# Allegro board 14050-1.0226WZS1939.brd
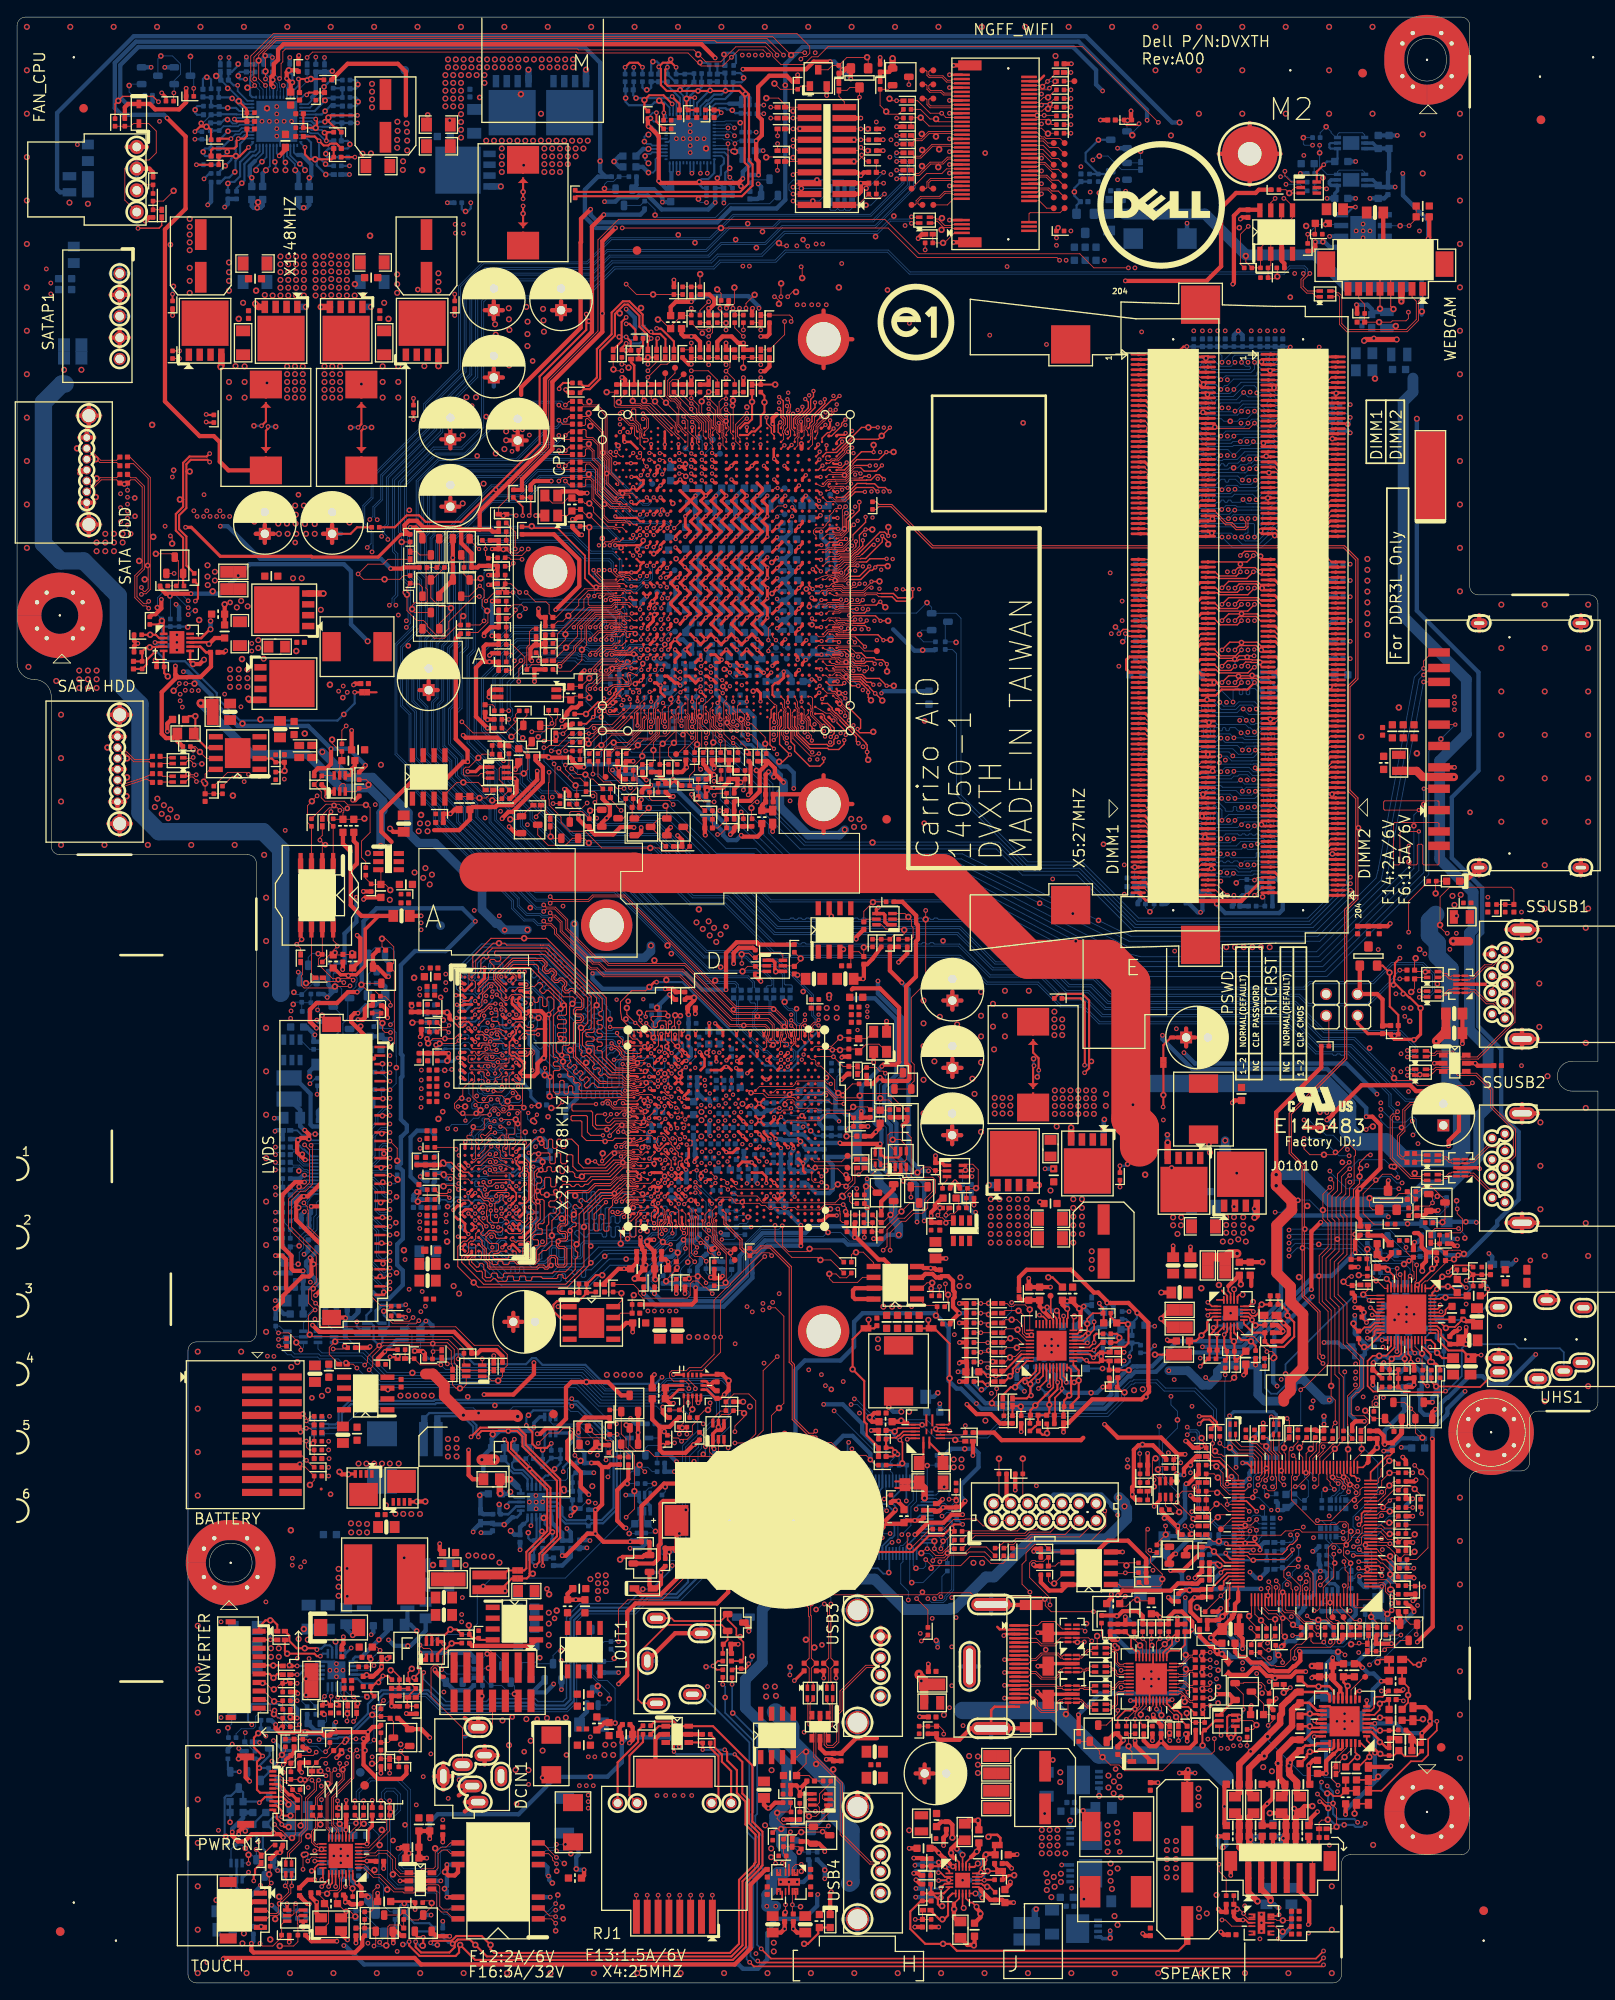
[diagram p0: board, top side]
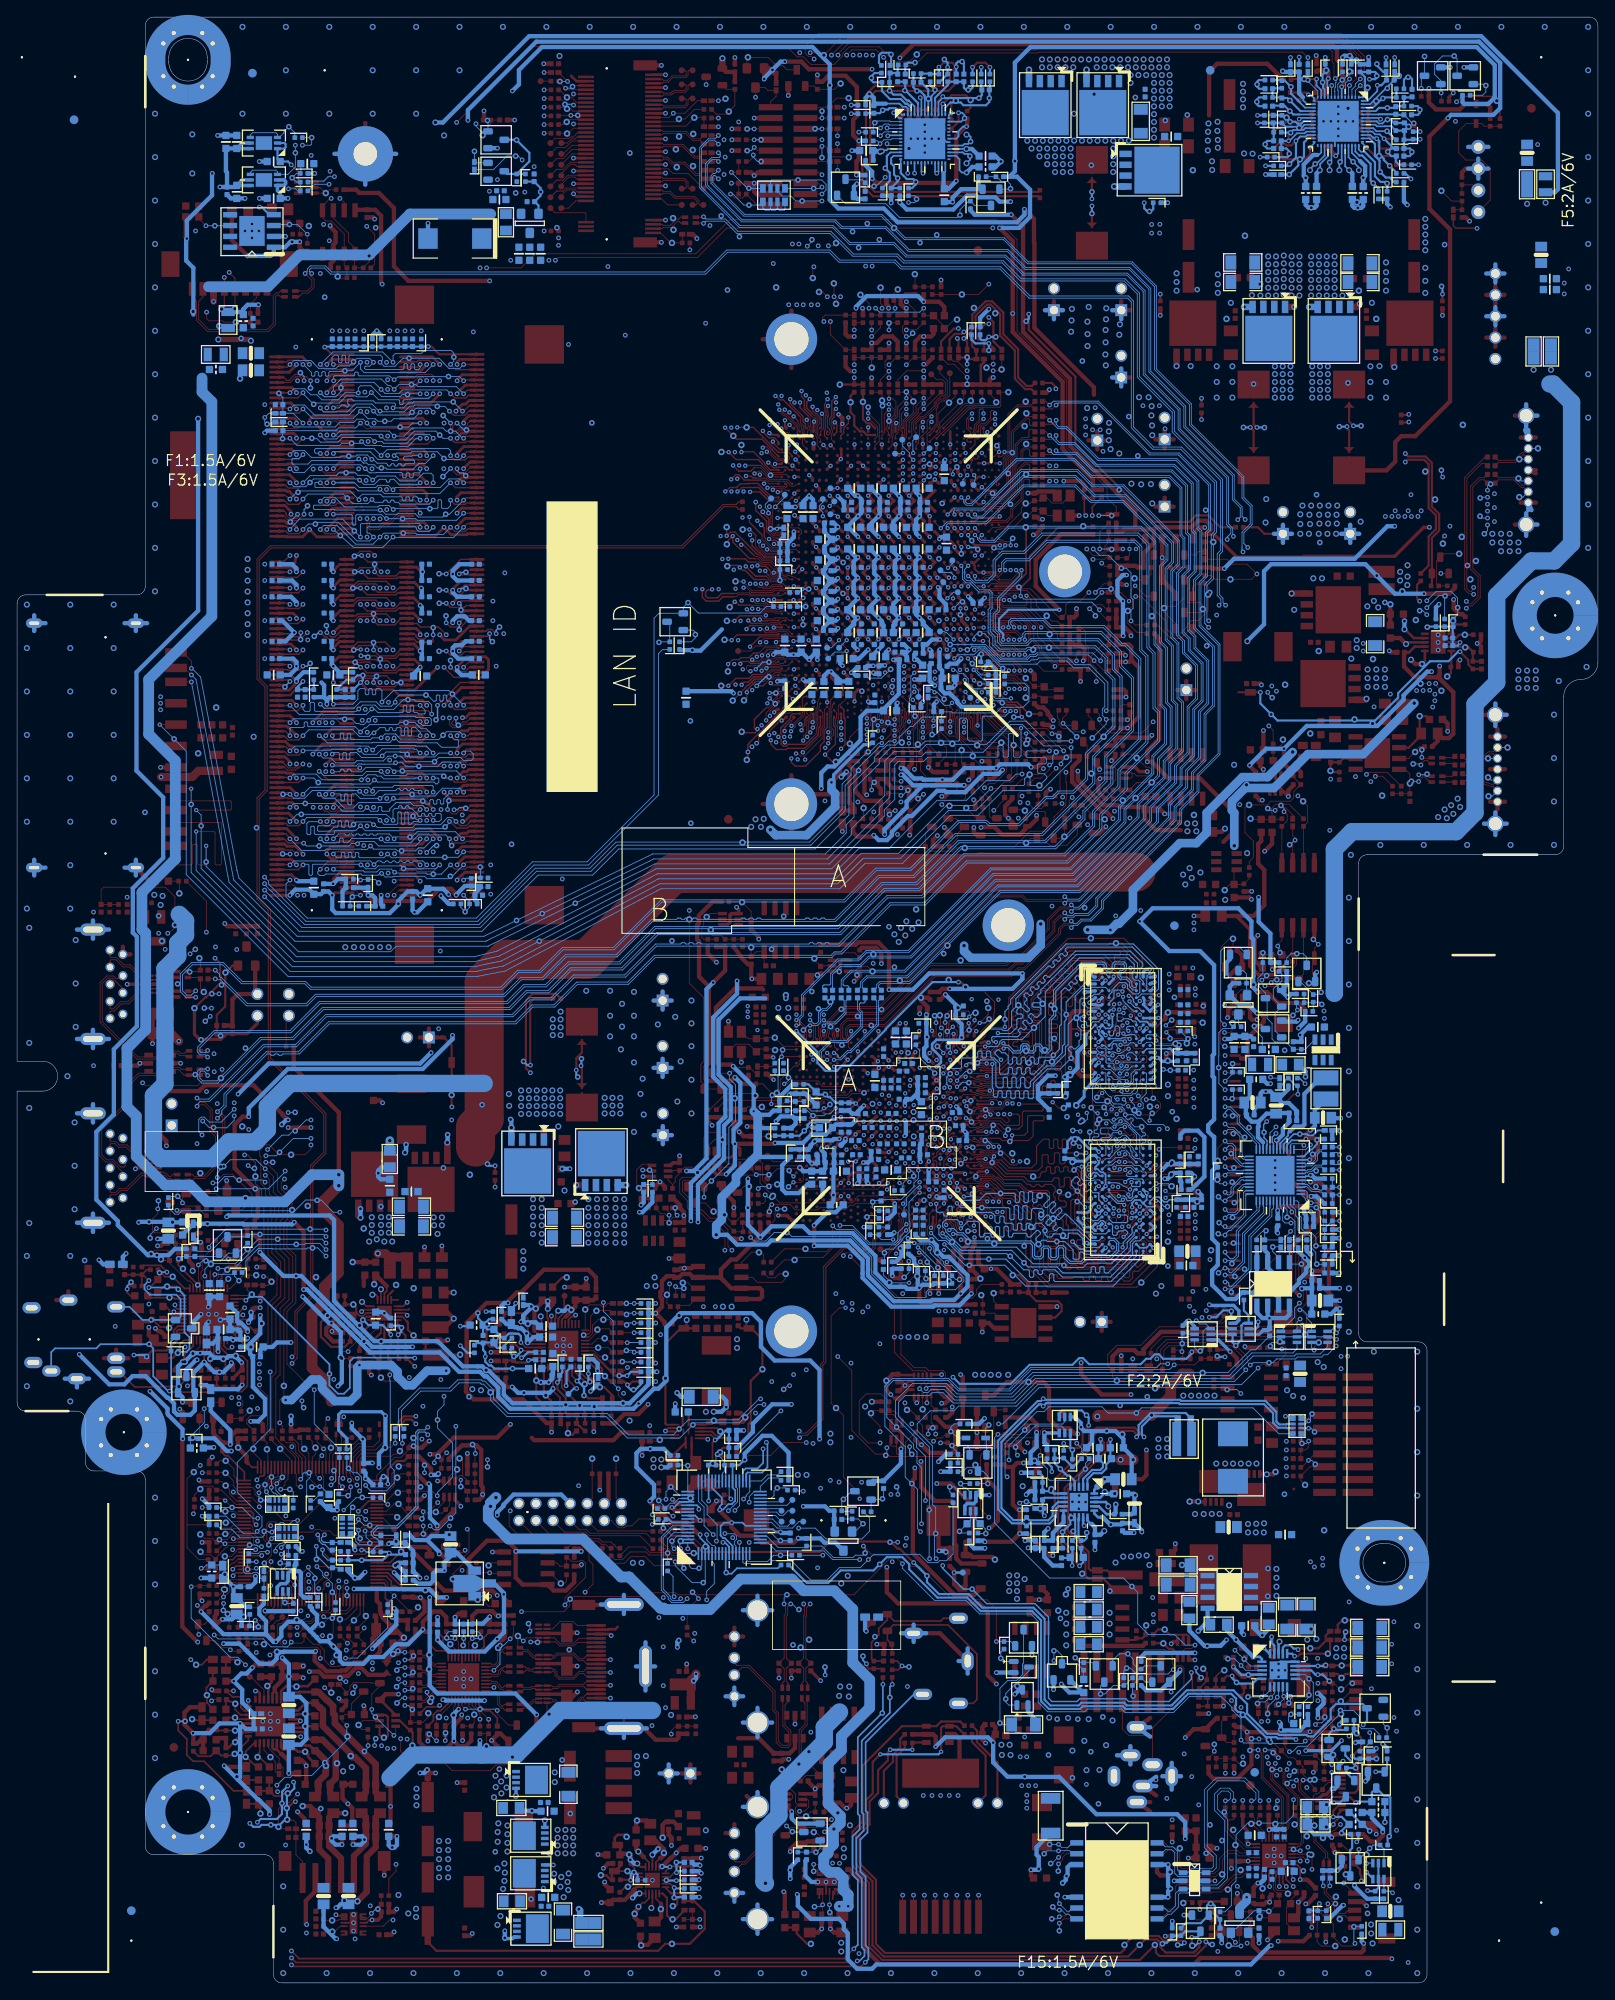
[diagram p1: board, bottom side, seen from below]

Outline 185 x 230 mm; copper layers: TOP, L2GND, L3, L4, L5GND, BOTTOM. Coordinates in mm from the lower left corner of the outline.
Outline path: 0,229 0,154.5 arc(0.59,153.09) 2,152.5 arc(3.41,151.91) 4,150.5 4,133 arc(4.29,132.29) 5,132 27,132 arc(27.71,131.71) 28,131 28,76 arc(27.71,75.29) 27,75 21,75 arc(20.29,74.71) 20,74 20,1 arc(20.29,0.29) 21,0 154,0 arc(154.71,0.29) 155,1 155,14 arc(155.29,14.71) 156,15 169,15 arc(169.71,15.29) 170,16 170,58.9 arc(170.29,59.61) 171,59.9 176,59.9 arc(176.71,60.19) 177,60.9 177,65.9 arc(177.29,66.61) 178,66.9 184,66.9 arc(184.71,67.19) 185,67.9 185,104.34 182,104.34 arc(180.25,106.09) 182,107.84 185,107.84 185,161.4 arc(184.71,162.11) 184,162.4 171,162.4 arc(170.29,162.69) 170,163.4 170,229 arc(169.71,229.71) 169,230 1,230 arc(0.29,229.71) 0,229 ; 24.75,51.4 25.25,51.4 arc(27.5,49.15) 25.25,46.9 24.75,46.9 arc(22.5,49.15) 24.75,51.4 ; 162.75,225.25 arc(165,227.5) 167.25,225.25 167.25,224.75 arc(165,222.5) 162.75,224.75 162.75,225.25

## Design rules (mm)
constraint set DEFAULT: min track width 0.127, pair gap 0.102
net group AUDIO_IO_40: nets RING2 SLEEVE
net group EUP-MW: nets EC_EUP EC_EUP_EN
net group GPU_ODT-MW: nets ODTA0 ODTA1
net group PWR_CHG_SR-DIFF0: nets PWR_CHG_SRN PWR_CHG_SRP
net group TRANSFORNER_20_10: nets MCT_R_1 XRF_TDC2
net group USB_OC-MW: nets USBOC01* USBOC02*
net group AGND: nets CHG_AGND SIO_AGND TPA3131_GVDD
net group AUDIO_AMP-MW: nets SYNC TPA3131_FAULT# TPA3131_SD TPA3131_SD1#
net group AUDIO_AMP_15: nets AMP_SPKR_L AMP_SPKR_R PORTC_SPK_L PORTC_SPK_L_1 PORTC_SPK_R PORTC_SPK_R_1 SPKR_IN_L SPKR_IN_R TPA3131_GAIN TPA3131_LINN TPA3131_LINN_1 TPA3131_MUTE TPA3131_PLIMIT TPA3131_RINN TPA3131_RINN_1
net group AUDIO_DMIC_MW: nets AUD_DMIC_CLK AUD_DMIC_CLK_R AUD_DMIC_CLK_R_1 AUD_DMIC_DATA AUD_DMIC_DATA_R
net group AUDIO_HDA: nets AUD_BEEP_C AUD_BEEP_R AUD_LINK_BCLK AUD_LINK_RST_N AUD_LINK_RST_N_R AUD_LINK_SDIN AUD_LINK_SDIN_1 AUD_LINK_SDO AUD_LINK_SDO_1 AUD_LINK_SDO_N AUD_LINK_SYNC BUZZER_SPKR_R PCH_AUD_RST_N PCH_AUD_RST_N_1 SENSE_B SLEEVE_G
net group AUDIO_IO: nets AUD_GP3 EAPD_DEPOP HPOL_CON HPOR_CON HPOUT-JD HPOUT-L HPOUT-R LINE2-VREFO LINEOUT-JD LINEOUT-L LINEOUT-R LINEOUT_C-L LINEOUT_C-R LINEOUT_CON-L LINEOUT_CON-R MIC2-L MIC2-L-1 MIC2-R MIC2-R-1 MIC2-VREFO-L MIC2-VREFO-R
net group AUDIO_IO_REF: nets JDREF MIC-CAP VRP
net group AUDIO_SPK_CN: nets SPKR_L+_C SPKR_L+_SNB SPKR_L-_C SPKR_L-_SNB SPKR_OUT_L+ SPKR_OUT_L- SPKR_OUT_R+ SPKR_OUT_R- SPKR_R+_C SPKR_R+_SNB SPKR_R-_C SPKR_R-_SNB TPA3131_BSNL TPA3131_BSNR TPA3131_BSPL TPA3131_BSPR
net group AZ_AUDIO: nets APU_SPKR AZ_BCLK_M AZ_RST_N_M AZ_SDIN1 AZ_SDIN2 AZ_SDOUT_M AZ_SYNC_M
net group CAL_8: nets MEM_MA_ZVDDIO MEM_MB_ZVDDIO P_RX_ZVDD P_TX_ZVDD SATA_CALRN SATA_CALRP USB_COMP_M USBSS_CALRN USBSS_CALRP
net group CHARGER_4_5-MW: nets AC_IN AC_OK# AC_PRES AC_PROTECT AD_IA AD_IA_HW1 AD_IA_HW2 AD_OFF AD_OFF_L BAT_ALERT BAT_IN# BAT_IN#_1 CHG_ON# PD4405_A PD4405_K PQ4206_D PQ4406_2 PQ4406_3 PQ4406_5 PQ4406_6 PQ4409_C PQ4409_E PWR_CHG_AD_OFF PWR_CHG_AD_OFF_R SYS_PRES
net group CLOCK-MWS: nets CK_48M_SIO CK_P_33M_EC CK_P_33M_SIO CLK_48M_SIO_C LPC_CLK0_R LPC_CLK1 LPC_CLK1_R PCH_CLK48_F SUSCLK_32_APU SUSCLK_32_APU_C X32K_X1 X32K_X2 X48M_X1 X48M_X2
net group CONVERTER_4_5-MW: nets LEDC_ISET LPF RT SSTCMP SSTCMP_1 STATUS VREF
net group CONVERTER_10_10: nets ISEN1 ISEN2 ISEN3 ISEN4 ISW OZ554_PWM RTN1 RTN2 RTN3 RTN4
net group CONVERTER_20_10: nets LDR LDR_1 OZ554_VIN SNB
net group DDR3_A_ADDR&CMD-MW: nets M_CAS_A_N M_MAA_A0 M_MAA_A1 M_MAA_A2 M_MAA_A3 M_MAA_A4 M_MAA_A5 M_MAA_A6 M_MAA_A7 M_MAA_A8 M_MAA_A9 M_MAA_A10 M_MAA_A11 M_MAA_A12 M_MAA_A13 M_MAA_A14 M_MAA_A15 M_RAS_A_N M_SBS_A0 M_SBS_A1 M_SBS_A2 M_WE_A_N
net group DDR3_A_CTRL-MW: nets M_ODT_A0 M_ODT_A1 M_SCKE_A0 M_SCKE_A1 M_SCS_A_N0 M_SCS_A_N1
net group DDR3_A_DATA-MW: nets M_DATA_A0 M_DATA_A1 M_DATA_A2 M_DATA_A3 M_DATA_A4 M_DATA_A5 M_DATA_A6 M_DATA_A7 M_DATA_A8 M_DATA_A9 M_DATA_A10 M_DATA_A11 M_DATA_A12 M_DATA_A13 M_DATA_A14 M_DATA_A15 M_DATA_A16 M_DATA_A17 M_DATA_A18 M_DATA_A19 M_DATA_A20 M_DATA_A21 M_DATA_A22 M_DATA_A23 M_DATA_A24 M_DATA_A25 M_DATA_A26 M_DATA_A27 M_DATA_A28 M_DATA_A29 M_DATA_A30 M_DATA_A31 M_DATA_A32 M_DATA_A33 M_DATA_A34 M_DATA_A35 M_DATA_A36 M_DATA_A37 M_DATA_A38 M_DATA_A39 M_DATA_A40 M_DATA_A41 M_DATA_A42 M_DATA_A43 M_DATA_A44 M_DATA_A45 M_DATA_A46 M_DATA_A47 M_DATA_A48 M_DATA_A49 M_DATA_A50 M_DATA_A51 M_DATA_A52 M_DATA_A53 M_DATA_A54 M_DATA_A55 M_DATA_A56 M_DATA_A57 M_DATA_A58 M_DATA_A59 M_DATA_A60 M_DATA_A61 M_DATA_A62 M_DATA_A63
net group DDR3_A_DM-MWS: nets M_MA_DM0 M_MA_DM1 M_MA_DM2 M_MA_DM3 M_MA_DM4 M_MA_DM5 M_MA_DM6 M_MA_DM7
net group DDR3_B_CTRL-MWS: nets M_ODT_B0 M_ODT_B1 M_SCS_B_N0 M_SCS_B_N1
net group DDR3_SEL_4_5-MW: nets SA0_DIM1 SA0_DIM2 SA1_DIM1 SA1_DIM2
net group DP_HPD-MW: nets DP0_HPD DP_HPD HDMI1_DET_APU HDMI1_DET_CON
net group EC_NPCE948L-4_5-MW: nets AC_IN_KBC# AC_OK#_ECIO AD_OFF_ECIO AGPIO84 BAT_IN#_ECIO CHG_ON#_ECIO EC_3P3_CTL EC_3P3_CTL_2 EC_3P3_CTL_3 EC_PSID EC_PWREN ECIO_IO_SMI_N ECIO_LPC_PME_N JENK# MODEL_ID_DET PCB_VER_ID RDY# SLP_S3_N_EC SLP_S5_N_EC TCK TDI TDO TMS
net group FAN_PWM: nets BKLT_ADJ CPU_FAN_CTRL_SIO CPU_FAN_TACH_SIO DPLVDS_PWMIN DPLVDS_PWMOUT LVDS_BL_ADJ SIO_LVDS_BL_ADJ
net group FCH_SW_4-MW: nets 0.775V_TRACK_GATE APU_S5_MUX_CTRL_D APU_S5_MUX_CTRL_R COMP_OUT1 COMP_OUT2 FCH_S5_POWER_COMP VDDNB_TRACK_GATE
net group FFS_4_5-MW: nets FALL_INT2 FFS_INT1 FFS_INT1_C FFS_INT2_APU FFS_INT2_C FFS_INT2_Q
net group GND: nets AMP_GND GND_AUD VSS_MECH
net group GPIO_4-MW: nets ADAPTOR_PSID ADAPTOR_PSID_R AGPIO3 AGPIO8 AGPIO11 AGPIO13 AGPIO14 AGPIO15 AGPIO24 AGPIO40 AGPIO66 AGPIO88 AGPIO89 BIST_DISABLE BIST_EN_INV BIST_ENABLE BIST_ENABLE_1 BOARD1 BOARD2 BOARD3 CORETYPE DP_2K_ZVSS DP_150_ZVSS DP_STEREOSYNC DP_STEREOSYNC_PU DPLVDS_HPD EAPD_DEPOP_1 EC_IMS EGPIO67 EGPIO70 EGPIO119 EGPIO131 EGPIO132 EGPIO145 GP11 GP24 GP26 GP27 GP32 GP33 GP34 GP63 GPIO17_THERMAL_INT GPIO19_CTF GPU_THERMAL_INT IO_SMI_N JACK_PSID LAN_DISABLE_N LPC_PME_N LVDS_DET_A* LVDS_DET_B* MINI_POWER_CTRL MPCIE_DISABLE_N NGFF_BT_DISABLE NGFF_DETECT_PCIE NGFF_DETECT_PCIE_C NGFF_DETECT_USB NGFF_DETECT_USB_C OSD_BIST_N OSD_DN OSD_DN_R OSD_MENU OSD_MENU_R OSD_MENU_SIO OSD_UP OSD_UP_R PSID_D PSID_D_1 PSID_G PW_CLEAR PWRCN_DET_N S0A3_GPIO S0A3_GPIO_G SIO_HDD_LED SIO_HDD_LED_1 SKEW1 SKEW2 SKEW3 SMBUS_ISP_G SPKR_DET SPKR_DET_C VDD_095_FB_H_CTL VDDGFX_PD WEBCAM_DET
net group GPU_ADDRESS-MW: nets MAA0 MAA1 MAA2 MAA3 MAA4 MAA5 MAA6 MAA7 MAA8 MAA9 MAA10 MAA11 MAA12 MAA13 MAA14 MAA_BA0 MAA_BA1 MAA_BA2
net group GPU_CTRL-MW: nets CASA0# CASA1# CKEA0 CKEA1 CSA0#_0 CSA1#_0 RASA0# RASA1# WEA0# WEA1#
net group GPU_DATA-MW: nets DQMA0 DQMA1 DQMA2 DQMA3 DQMA4 DQMA5 DQMA6 DQMA7 MDA0 MDA1 MDA2 MDA3 MDA4 MDA5 MDA6 MDA7 MDA8 MDA9 MDA10 MDA11 MDA12 MDA13 MDA14 MDA15 MDA16 MDA17 MDA18 MDA19 MDA20 MDA21 MDA22 MDA23 MDA24 MDA25 MDA26 MDA27 MDA28 MDA29 MDA30 MDA31 MDA32 MDA33 MDA34 MDA35 MDA36 MDA37 MDA38 MDA39 MDA40 MDA41 MDA42 MDA43 MDA44 MDA45 MDA46 MDA47 MDA48 MDA49 MDA50 MDA51 MDA52 MDA53 MDA54 MDA55 MDA56 MDA57 MDA58 MDA59 MDA60 MDA61 MDA62 MDA63
net group GPU_JTAG_4-6-MW: nets JTAG_TCK_VGA JTAG_TDI_VGA JTAG_TDO_VGA JTAG_TMS_VGA JTAG_TRST#_VGA
net group GPU_OTHER_4-6-MW: nets CLKTESTA CLKTESTA_C CLKTESTB CLKTESTB_C CTF_TRIP CTFB GPIO19_CTF_R GPIO_SVC GPIO_SVD GPIO_SVT GPU_CLKA0_T GPU_CLKA1_T GPU_GPIO16 GPU_SCL GPU_SDA GPU_THERM_SHUTDOWN* GPU_VCC3_CTL GPU_VCC3_CTL_2 GPU_VCC3_CTL_3 GPU_WAKEB GPU_XO_IN GPU_XO_IN2 MEM_CALRP0 MLPS_EN# PCIE_CALR_RX PCIE_CALR_TX PS_0 PS_1 PS_2 PS_3 VRAM_ZQ1 VRAM_ZQ2 VRAM_ZQ3 VRAM_ZQ4
net group GPU_VREF: nets GPU_VREFG MVREFDA MVREFSA VRAM1_VREFCA VRAM1_VREFDQ VRAM2_VREFCA VRAM2_VREFDQ VRAM3_VREFCA VRAM3_VREFDQ VRAM4_VREFCA VRAM4_VREFDQ
net group HDMI-MW: nets CFG DCIN_EN DDCBUF EQ ISET PD_N PRE REXT SB5_33_CT1 SB5_33_CT2 VCC5_DDC_HDMI
net group HDMI_DDA-MW: nets HDMI1_DATA_APU HDMI1_DATA_APU_SRC HDMI1_DATA_CON
net group HDMI_DDC-MW: nets HDMI1_CLK_APU HDMI1_CLK_APU_SRC HDMI1_CLK_CON
net group HDMI_PWR: nets V_5P0_HDMI_CONN_L
net group HDT-MW: nets APU_ALERT# APU_DBRDY APU_DBREQ APU_DBREQ# APU_SVD APU_SVT APU_TCK APU_TDI APU_TDO APU_TMS APU_TRST HDT_C_M1 HDT_C_M2 HDT_C_M3 HDT_PW_M3 HDT_PW_M4 HDT_RST0 HDT_RST1 HDT_TRST HDT_VDDIO_SUS
net group LAN_OTHER_4-5-MW: nets LAN_RSET LANCLK_REQ_N LANCLK_REQ_U_N RTL_ISOLATE_N RTL_ISOLATE_N_1 RTL_ISOLATE_N_2
net group LED_10_6: nets APU_SATA_LED_N BATT_AMBER_LED# BATT_AMBER_LED#_C BATT_WHITE_LED# BATT_WHITE_LED#_C LAN_LEDACT_R# LINK_ACTIVITY_N LINK_PWR PB_IN_SW1 PCH_SATA_LED_1 PCH_SATA_LED_R PWR_LED_YELLOW_C PWR_LED_YELLOW_C2 SATA_LED_N_C_1 SIO_GREEN SIO_GREEN_PWM SIO_GREEN_PWM_C_1 SIO_YELLOW SPEED_100*_CON SPEED_100_N SPEED_1000*_CON SPEED_1000_N SUS_LED_GREEN_C SUS_LED_GREEN_C2
net group LPC-MW: nets EXT_RST# FWH_ID0 INIT_3V LAD0_FWH0 LAD0_FWH0_EC LAD1_FWH1 LAD1_FWH1_EC LAD2_FWH2 LAD2_FWH2_EC LAD3_FWH3 LAD3_FWH3_EC LDRQ# LDRQ#_EC LFRAMEJ_FW4 LFRAMEJ_FW4_EC LPC_PD_N LPC_TPM PLTRST*_EC SER_IRQ
net group M_EVENT_4_5-MW: nets MEM_MA_EVENT_L SIO_MEM_EVENT_L SIO_MEM_EVENT_L_B SIO_MEM_EVENT_L_C
net group MEM_VREF: nets APU_M_VREF_SUS APU_M_VREFDQ_SUS DIMM_APU_VREF DIMM_DQ_APU_VREF_MA DIMM_DQ_APU_VREF_MB MEM_VREFCA_SUS
net group NGFF_CLCCK-MW: nets NGFF_CLKREQ0_N NGFF_CLKREQ1_N SUSCLK_NGFF
net group NGFF_OTHER-MW: nets NGFF_ALERT# NGFF_ALERT_N NGFF_CLKREQ0_NGFF# NGFF_CLKREQ1_APU# NGFF_CLKREQ1_N_TP NGFF_PEWAKE0_N NGFF_POWER_CTRL_1 NGFF_W_DISABLE1_N NGFF_W_DISABLE2_N
net group OSCILLATION-MW: nets LAN_XTALI LAN_XTALO XTALIN XTALOUT
net group OTHER_4_5-MW: nets 1117_ADJ APU_PROCHOT# APU_PWNBTN_N APU_SIC APU_SID APU_SVC APU_VDD_33_18_SEL ECIO_APU_PROCHOT# GFX_SVC GFX_SVD GFX_SVT KDAT MCLK MDAT PB_IN_N_1 PB_IN_N_2 PME#_M SVC_VDD SVC_VDD_GFX SVD_VDD SVD_VDD_GFX SVT_VDD SVT_VDD_GFX SYS_FAN_TACH1_1 SYS_FAN_TACH1_2 SYSTEM_FAN_PWM1_1 TP_DET VR_HOT WAKE_N_APU
net group PANEL_CONTROL-MW: nets APU_LVDS_BL_ADJ BIST_EN_SIO BIST_PIN25 BKLT_EN BKLT_EN1 BUFFER1_M4 DPLVDS_BL_EN DPLVDS_PANEL_VCC LVDS_BL_EN_1 LVDS_DET_B_C* LVDS_PU_5 LVDS_PU_5_1 LVDS_PU_5_2 LVDS_PU_6 LVDS_PU_24 PANEL_ON_1 PANEL_ON_2 PANEL_ON_3 PANEL_ON_4 PANEL_ON_5 PANEL_SEL1_CABLE PANEL_SEL1_CABLE_EC PANEL_SEL2_CABLE PANEL_SEL2_CABLE_EC PANEL_SEL3_CABLE PANEL_SEL3_CABLE_EC S_LVDS_BL_EN SCALAR_SIO_PU
net group POWER_10_10: nets COMPNB_R PWR_FCH_S5 SIO_VREF VBAT_SB_N VBAT_SIO
net group POWER_40_5: nets 3D3V_AUX_EC AVCC_EC DPLL_PVDD HM_VCCP HM_VCCP_R SIO_AVCC3 SIO_MAIN_VCC3 SIO_VCORE SPV10 SPV18
net group POWER_50_5: nets 3D3V_VGA_S0 3V_VA +3VL +5VL AVCC33_2136 DPLL_VDDC DVCC33_2136 SWR_LX SWR_V12 USBVCC01_E V_5_CODEC
net group POWER_OTHER_40_5: nets 1P5V_LPS_APU 3D3V_RUN_FFS 19V_AMP_AVCC 19V_AMP_PVCC APU_VDDIO_AZ FCH_0.775_S5 V_1P5_HDMI
net group POWER_RTC_35_5: nets VBAT1 VBAT1_R VBAT2
net group PWM_10_10: nets 1P5_5930_FB 1P5_5930_VCNTL 1P5V_GUP_FB_M 1P5V_GUP_FB_M1 62882_COMP_R 62882_FB_VSEN 62882_NTC_R AD+_G_1 AD+_G_2 AUD_LINK_RST_N_2 BIST_DISABLE_1 BIST_EN DC_IN_D DDR_VREF_S3 DIFFNB_R EAPD_DEPOP_2 ILIM_R ILIMNB_R LAN_DISABLE_N_1 LAN_DISABLE_N_2 LED_5VSB OSD_BIST_N_1 PM_DPRSLPVR PRW_VGA_CORE_RBIAS PSI# PWR_1D8V_EN PWR_1D8V_FB PWR_1D8V_VCC PWR_3D3V_ENTRIP2 PWR_3D3V_FB PWR_3D3V_FB2 PWR_5V3V_EMN PWR_5V3V_PGOOD PWR_5V3V_TON PWR_5V_ENTRIP1 PWR_5V_FB1 PWR_CHG_ACDET PWR_CHG_CMPIN PWR_CHG_CMPIN_R PWR_CHG_CMPIN_RR PWR_CHG_IOUT PWR_CHG_NC PWR_COMP_R PWR_CPU_COMP PWR_CPU_COMPNB PWR_CPU_CSCOMP PWR_CPU_CSCOMPNB PWR_CPU_CSP1 PWR_CPU_CSP1NB PWR_CPU_CSP2 PWR_CPU_CSP2NB PWR_CPU_CSREF PWR_CPU_CSREFNB PWR_CPU_CSSUM PWR_CPU_CSSUMNB PWR_CPU_DIFF PWR_CPU_DIFFNB PWR_CPU_DROOP PWR_CPU_DROOPNB PWR_CPU_FB PWR_CPU_FBNB PWR_CPU_ILIM PWR_CPU_ILIMNB PWR_CPU_IOUT PWR_CPU_IOUTNB PWR_CPU_PHCONFIG PWR_CPU_ROSC PWR_CPU_SR PWR_CPU_TEENSE PWR_CPU_TSENSENB PWR_CPU_VRMP PWR_DIFF_R PWR_GFX_COMP PWR_GFX_COMP_FB PWR_GFX_CSCOMP PWR_GFX_CSP1 PWR_GFX_CSP2 PWR_GFX_CSREF PWR_GFX_CSSUM PWR_GFX_DIFF PWR_GFX_DIFF_R PWR_GFX_DROOP PWR_GFX_FB PWR_GFX_ILIM PWR_GFX_ILIM_R PWR_GFX_IOUT PWR_GFX_PHCONFIG PWR_GFX_ROSC PWR_GFX_SR PWR_GFX_TSENSE PWR_GFX_VR_HOT PWR_GFX_VRMP PWR_GFX_VSS PWR_VDDP_CS PWR_VDDP_EN PWR_VDDP_FB PWR_VDDP_FB_R PWR_VDDP_PG PWR_VDDP_RF PWR_VDDQ_CS PWR_VDDQ_EN PWR_VDDQ_FB PWR_VDDQ_SENSE PWR_VDDQ_TON PWR_VDDQ_VDD PWR_VDDQ_VDDP PWR_VDDQ_VTTREF PWR_VGA_CORE_COMP PWR_VGA_CORE_DPRSLPVR PWR_VGA_CORE_IMON PWR_VGA_CORE_ISEN1 PWR_VGA_CORE_ISEN2 PWR_VGA_CORE_ISUM- PWR_VGA_CORE_NTC PWR_VGA_CORE_ON PWR_VGA_CORE_PGOOD PWR_VGA_CORE_PSI# PWR_VGA_CORE_RTN PWR_VGA_CORE_VSEN PWR_VGA_CORE_VW PWR_VTT_EN TSVDD VDDC_CT VR_TT# VREG_PCIAUX_PCH VREG_PCIAUX_PCH_1 VSUM_RC VSUM_RR
net group PWM_20_10: nets AUD_REGREF BQ24737_REGN CBN CBP CPU_BST1_SW1 CPU_BST2_SW2 CPVEE D2_M DPLVDS_PIN12 DPLVDS_PIN16 PWR_1D8V_BOOT PWR_1D8V_BOOT_A PWR_1D8V_FB_1 PWR_1D8V_VOUT PWR_3D3V_BOOT2 PWR_3D3V_BOOT2_R PWR_3D3V_LDO3 PWR_5V3V_ENLDO PWR_5V3V_LDO5 PWR_5V_BOOT1 PWR_5V_BOOT1_R PWR_5V_BYP1 PWR_5V_SNB PWR_CHG_BTST PWR_CHG_BTST_1 PWR_CHG_ILIM PWR_CPU_BST1 PWR_CPU_BST2 PWR_GFX_BST1 PWR_GFX_BST1_SW1 PWR_VDDP_BOOT_R PWR_VDDQ_BOOT PWR_VDDQ_BOOT_L PWR_VDDQ_SNB PWR_VGA_CORE_BOOT1 PWR_VGA_CORE_FB PWR_VGA_CORE_FB2 PWR_VGA_CORE_VCCP PWR_VGA_CORE_VDD PWR_VGA_CORE_VIN PX_EN SIO_VIN2 SIO_VIN3 SIO_VIN4 SIO_VIN5 TESTEN V_0P675_S3 VREF_1
net group PWM_30_12: nets PWR_CHG_VCC PWR_CPU_VCC PWR_CPU_VDD PWR_CPU_VDDNB PWR_GFX_VCC PWR_GFX_VDD
net group PWM_PHASE: nets PWR_3D3V_LGATE2 PWR_3D3V_UGATE2 PWR_5V_LGATE1 PWR_5V_UGATE1 PWR_CHG_HIDRV PWR_CHG_LODRV PWR_CPU_HG1 PWR_CPU_HG2 PWR_CPU_LG1 PWR_CPU_LG2 PWR_GFX_HG1 PWR_GFX_LG1 PWR_VDDP_LGATE PWR_VDDP_UGATE PWR_VDDQ_LGATE PWR_VDDQ_UGATE PWR_VGA_CORE_LGATE1A PWR_VGA_CORE_LGATE1B PWR_VGA_CORE_UGATE1
net group PWR_EN_4-MW: nets 0D95V_S0_EN 0P95V_MAIN_APU_M 1P5_5930_EN 3P3_VGA_1P8_EN +1.5V_GPU_PG APU_DIS_1 APU_DIS_2 APU_DIS_3 APU_S5_MUX_CTRL DGPU_PWROK_0D95V DIS_EN_0D95_RUN_R EVAL_PE_L EVAL_PWREN EVAL_PWRGD EVAL_PWRGD_0D95 EVAL_PWRGD_1D5 OZ554_ENA PWR_FCH_REF PWR_FCH_VCNTL RUN_0P95_EN1 RUN_0P95_EN2 RUN_0P95_EN3 RUN_0P95_EN4 RUN_EN1 RUN_EN2 RUN_EN_1P8V RUNPWR_R6 SB3V_EN SIO_AMD_SVID_EN V_VCORE_EN VCC5_33_CT1 VCC5_33_CT2 VCC5_33_EN VDDGFX_EN VDDGFX_EN_1 VDDGFX_EN_2 VGA_1P8_EN1 VGA_1P8_EN2 VGA_1P8_EN3 VGA_1P8_EN4 VRAM_0D95_EN_D VRAM_0D95_EN_SW
net group PWR_EN_4_10-MW: nets USB_EN USB_EN1 USB_EN2 VBYP_2
net group PWRGD&RST_4-MW: nets 1D5V_S3_PG_1 1P5_5930_PG 1P5V_S3_PG 1P8V_PWR_PG 3V_5V_POK AMD_RST# APU_PWRGD APU_PWRGD_BUF APU_VRM_PWRGD DDR3_DRAMRST_N DDR3_DRAMRST_N_A_1 DDR3_DRAMRST_N_B_1 DGPU_PWROK DGPU_PWROK_1D5V DRAM_RST DRAM_RST_R FP_RST_N GFX_VRM_PWRGD ICH_RSMRST_N_R KBRST_N LAN_DISABLE_N_3 LAN_DISABLE_N_4 LAN_DISABLE_V3 LDT_RST LDT_RST#_BUF MEM_RST NB_VRM_PWRGD NGFF_POWER_CTRL_V2 PCIE_RST# PCIE_RST_N PCIE_RST_N_A PCIRST1# PCIRST3# PLTRST*_SIO PLTRST_LAN_N PLTRST_N PLTRST_SL_N PWRBTN_N PWRGD_3V PWRGD_3V_B_1 PWRGD_3V_D PWRGD_3V_G PWRGD_3V_LL PWRGD_PS_L PWRGD_PS_L1 PWRGD_PS_L2 PWRGOOD_GPU PWROK3_1 PWROK3_1_R PWROK3_2 PWROK3_2_R RSMRST*_R RSMRST_N RSMRST_N_1 RSMRST_N_FCH SIO_PCIRSTIN# SIO_PSON_N SLP_S3_N SLP_S3_N_1 SLP_S3_N_G SLP_S3_N_R SLP_S3_N_R3 SLP_S3_N_R_1 SLP_S3_N_R_2 SLP_S3_N_R_3 SLP_S5_N SLP_S5_N_C SYS_PWRGD SYS_PWRGD_G SYS_PWRGD_HV SYS_PWRGD_HV_1 SYS_PWRGD_HV_2 VCORE_PWROK VDDGFX_PWROK WAKE_N
net group SD_CARD-MWS: nets SD_CD_BD SD_CLK_BD SD_CLK_CH_C SD_CMD_BD SD_CMD_CH_C SD_DATA0_BD SD_DATA0_CH_C SD_DATA1_BD SD_DATA1_CH_C SD_DATA2_BD SD_DATA2_CH_C SD_DATA3_BD SD_DATA3_CH_C SD_LED_BD SD_LED_BD_A SD_PWRCTL_CH SD_WP_BD
net group SENSE_4-MW: nets VDDCR_CPU_SENSE VDDCR_GFX_SENSE VDDCR_NB_SENSE VDDP_SENSE
net group SIO_IT8739-4_5-MW: nets EC_A20GATE EC_HDMI_PD_N EC_LAN_DISABLE_N IMS KBCLK SIO_ATXPG SIO_CE_N SIO_CLK_DB SIO_COPEN# SIO_DAT_DB SIO_EUP_EN# SIO_HOLD# SIO_INT# SIO_INT_C SIO_PWNBTN_N SIO_SCK SIO_SCK_R SIO_SI SIO_SO SIO_VIN1 SIO_WP# SIO_WRST# SW_ON_N_SIO SYS_3VSB
net group SIO_IT8739-4_12-MW: nets A20GATE
net group SMBUS-MW: nets BATA_SCL_1 BATA_SDA_1 DPLVDS_EDIDCLK DPLVDS_EDIDCLK_C DPLVDS_EDIDSDA DPLVDS_EDIDSDA_C DPLVDS_FWCLK DPLVDS_FWSDA DPLVDS_ISPCLK DPLVDS_ISPDAT EC_SMB2_CLK EC_SMB2_DATA GPIO_VGA_03_DATA GPIO_VGA_03_DATA_R GPIO_VGA_04_CLK GPIO_VGA_04_CLK_R ISP_CLK1 ISP_DAT1 M1_SMB_CLK M1_SMB_DATA SIO_DEBUG_RX SIO_DEBUG_TX SIO_SMB2_CLK SIO_SMB2_DATA SIO_SMCLK0 SIO_SMCLK0_D SIO_SMDAT0 SIO_SMDAT0_D SMB0_CLK SMB0_CVT_CLK SMB0_CVT_DATA SMB0_DATA SMB1_CLK SMB1_DATA SMBUS_ISP SMBUS_MS
net group SPI-MW: nets GPIO_8_ROMSO GPIO_9_ROMSI GPIO_22_ROMCS# ROM_CS# ROM_RST# ROM_SI_D3 ROM_SO_C4 SPI_33_18_PU1 SPI_33_18_PU2 SPI_CS0_N SPI_DATAIN SPI_DATAOUT SPI_MISO_ROM_1 SPI_MOSI_1 SPI_WP# SST_HOLDJ_1 SST_HOLDJ_1_R
net group SPI_CLK_8-MW: nets GPIO_10_ROMSCK ROM_SLK_D4 SPI_CLK SPI_CLK_1
net group TP-MW: nets APU_TEST0 APU_TEST1 APU_TEST2 APU_TEST4 APU_TEST5 APU_TEST6 APU_TEST9 APU_TEST10 APU_TEST11 APU_TEST14 APU_TEST15 APU_TEST16 APU_TEST17 APU_TEST28_H APU_TEST28_L APU_TEST31 APU_TEST37 APU_TEST410 APU_TEST411 EC_SCI EC_VCORF RSVD_AN30 RSVD_U30 RSVD_U31 T_DP_BLON T_DP_DIGON TEMPIN0 TEMPIN1 TEMPIN2 TEMPINR TEST18_M TEST19_M TP_GPU_CLKREQ# TP_NGFF_COEX1 TP_NGFF_COEX2 TP_NGFF_COEX3 TP_NGFF_LED1 TP_NGFF_LED2 TP_NGFF_MLDIR USBCLK_TP
net group VRD_4_12-MW: nets H_VID0 H_VID1 H_VID2 H_VID3 H_VID4 H_VID5 H_VID6 PWR_VGA_CORE_VID0 PWR_VGA_CORE_VID1 PWR_VGA_CORE_VID2 PWR_VGA_CORE_VID3 PWR_VGA_CORE_VID4 PWR_VGA_CORE_VID5 PWR_VGA_CORE_VID6
net group VRD_10_10: nets VSS_SENSE
net group WLAN_CLINK_4_10-MW: nets CLINK_CLK_LAN CLINK_DATA_LAN CLINK_RST_LAN_N

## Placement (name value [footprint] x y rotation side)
AFTP1  AFTE14P-GP  [AFTE14P-75]  35.59 57.78 0 top
BAT2  ACES-CONN20G-GP  [50290-0100N-001]  32 64.14 270 top
BT1  BAT-AAA-BAT-034-K01-GP  [AAA-BAT-034-K01]  83.37 54.11 180 top
BTRST1  JOWLE-CON2-5-GP  [A2541WV0-1EX2PA-6T]  156.88 114.43 270 top
C1  SCD1U16V2KX-3DLGP  [C402H22]  157.39 194.31 0 bottom
C2  SC10U6D3V3MX-DL-GP  [C603H36]  41.31 109.98 0 bottom
C3  SC10U6D3V3MX-DL-GP  [C603H36]  42.58 109.98 0 bottom
C4  SC4D7U10V3KX-DL-GP  [C603H36]  40.8 39.29 90 top
C5  SCD47U25V3KX-1-DL-GP  [C603H36]  34.83 30.35 90 bottom
C6  SCD1U16V2KX-3DLGP  [C402H22]  40.29 109.98 0 bottom
C7  SC1U10V2KX-1GP  [C402H22]  34.07 86.49 180 bottom
C8  SC1KP50V2KX-1DLGP  [C402H22]  40.95 34.67 270 top
C9  SC1U10V2KX-1GP  [C402H22]  31.53 86.11 90 bottom
C10  SC100P50V2JN-3DLGP  [C402H22]  38.01 38.61 0 top
C11  SC1U10V2KX-1GP  [C402H22]  31.53 83.06 90 bottom
C14  SCD01U50V2KX-1DLGP  [C402H22]  35.64 109.68 180 bottom
C15  SC1KP50V2KX-1DLGP  [C402H22]  141.38 191.9 0 bottom
C20  SC4D7U10V3KX-DL-GP  [C603H36]  32.77 111.84 270 bottom
C32  SCD1U25V3ZY-1-LL-GP  [C603H36]  50.55 50.34 270 top
C33  SC27P50V2JN-2-LL-GP  [C402H22]  44.71 34.01 0 top
C35  SC330P100V3JN-GP  [C603H36]  40.93 41.78 270 bottom
C36  SC1U100V6KX-3-GP  [C1206H75]  34.12 42.8 0 bottom
C37  SC1U100V6KX-3-GP  [C1206H75]  36.36 42.8 0 bottom
C38  SC1U100V6KX-3-GP  [C1206H75]  26.7 39.24 90 bottom
C39  SC1U100V6KX-3-GP  [C1206H75]  26.7 36.96 90 bottom
C40  SC1U100V6KX-LL-GP  [C1206H71]  26.7 41.53 90 bottom
C41  SCD1U16V2KX-3DLGP  [C402H22]  65.44 177.04 270 top
C42  SCD1U16V2KX-3DLGP  [C402H22]  65.44 177.93 270 top
C43  SCD1U25V2KX-LL-GP  [C402H22]  38.26 34.92 180 top
C44  SCD1U16V2KX-3DLGP  [C402H22]  65.44 176.15 270 top
C45  SCD1U16V2KX-3DLGP  [C402H22]  65.44 175.26 270 top
C46  SCD1U16V2KX-3DLGP  [C402H22]  131.35 159.38 90 bottom
C48  SC10U25V5KX-DL-GP  [C805H58]  8.29 214.12 0 bottom
C50  SC5D6P50V2CN-1DLGP  [C402H22]  65.95 171.96 0 top
C52  SC5D6P50V2CN-1DLGP  [C402H22]  65.95 173.86 180 top
C55  SC4D7U6D3V3KX-DLGP  [C603H36]  137.83 152.91 90 bottom
C57  SC10P50V2JN-4DLGP  [C402H22]  65.95 152.15 180 top
C58  SC8P50V2DN-1DL-GP  [C402H22]  65.95 150.11 0 top
C60  SCD1U16V2KX-3DLGP  [C402H22]  131.35 156.97 90 bottom
C61  SCD01U25V2KX-3GP  [C402H22]  68.99 138.68 270 top
C65  SC1KP50V2KX-1DLGP  [C402H22]  145.7 150.88 0 bottom
C66  SC100P50V2JN-3GP  [C402H22]  80.17 139.83 90 top
C67  SCD01U16V2KX-3GP  [C402H22]  72.42 137.54 90 top
C72  SC10U6D3V3MX-DL-GP  [C603H36]  162.21 146.43 180 top
C73  SC4D7U6D3V3KX-GP  [C603H36]  163.48 146.43 0 top
C74  SCD1U16V2KX-3GP  [C402H22]  159.8 146.43 0 top
C75  SC2D2U10V3KX-1DLGP-U  [C603H36]  160.94 146.43 180 top
C76  SC150P50V2JN-3DLGP  [C402H22]  149.51 56.77 0 bottom
C77  SCD01U25V2KX-3GP  [C402H22]  78.27 143.51 0 top
C78  SC1U10V2KX-1DLGP  [C402H22]  62.26 159.77 270 top
C84  SCD1U16V2KX-3DLGP  [C402H22]  37.63 17.53 180 bottom
C87  SCD1U16V2KX-3GP  [C402H22]  43.82 34.01 0 top
C88  SCD1U16V2KX-3GP  [C402H22]  44.1 30.96 90 top
C91  SCD1U16V2KX-3DLGP  [C402H22]  163.1 117.47 90 top
C94  SCD1U25V3KX-GP  [C603H36]  52.99 138.05 0 top
C95  SC10U10V5KX-2GP  [C805H54]  45.25 135.64 0 top
C99  SC1U10V2KX-1DLGP  [C402H22]  158.15 123.19 180 top
C100  SC1U10V2KX-1GP  [C402H22]  159.42 123.19 180 top
C101  SCD1U16V2KX-3DLGP  [C402H22]  49.44 135.76 90 top
C103  SCD1U16V2KX-3DLGP  [C402H22]  144.05 207.01 0 top
C104  SC10U10V5KX-2DLGP  [C805H50]  168.18 111.12 90 top
C105  SC10U10V5KX-2GP  [C805H54]  168.18 113.41 270 top
C106  SCD1U16V2KX-3GP  [C402H22]  172.12 125.73 180 top
C109  SC10U6D3V3MX-DL-GP  [C603H36]  5.62 199.39 90 bottom
C110  SC1U25V3KX-1-DLGP  [C603H36]  5.62 198.12 90 bottom
C111  SCD1U16V2KX-3DLGP  [C402H22]  163.1 97.03 90 top
C112  SC10U10V5KX-2DLGP  [C805H50]  6.64 202.18 0 bottom
C113  SCD1U16V2KX-3DLGP  [C402H22]  163.1 96.01 90 top
C114  SCD01U50V2KX-1DLGP  [C402H22]  12.48 175.48 270 top
C115  SCD01U50V2KX-1DLGP  [C402H22]  12.48 176.49 270 top
C118  SCD01U50V2KX-1DLGP  [C402H22]  12.48 177.51 270 top
C119  SCD01U50V2KX-1DLGP  [C402H22]  12.48 178.52 270 top
C121  SC100P50V2JN-3GP  [C402H22]  156.12 84.2 180 top
C122  SCD1U16V2KX-3DLGP  [C402H22]  65.44 185.04 270 top
C126  SC22P50V2JN-4GP  [C402H22]  163.41 85.34 0 top
C127  SC10U6D3V3MX-DL-GP  [C603H36]  159.93 86.49 270 top
C129  SC10U6D3V3MX-DL-GP  [C603H36]  159.16 84.45 180 top
C130  SCD1U25V2KX-GP  [C402H22]  167.17 84.96 0 top
C131  SCD1U16V2KX-3DLGP  [C402H22]  161.27 85.45 270 top
C132  SC100P50V2JN-3GP  [C402H22]  156.24 81.15 180 top
C134  SC100P50V2JN-3DLGP  [C402H22]  172.42 83.31 180 top
C138  SC4D7U6D3V3KX-DLGP  [C603H36]  168.54 81.53 180 top
C139  SC4D7U6D3V3KX-DLGP  [C603H36]  170.47 80.39 90 top
C140  SC2D2U10V3KX-1DLGP-U  [C603H36]  167.93 78.38 180 top
C141  SCD01U50V2KX-1DLGP  [C402H22]  16.29 140.46 270 top
C142  SCD01U50V2KX-1DLGP  [C402H22]  16.29 141.48 270 top
C144  SC10U10V5KX-2DLGP  [C805H50]  170.85 77.98 180 top
C145  SCD1U16V2KX-3DLGP  [C402H22]  169.2 78.11 0 top
C146  SC10U10V5KX-2DLGP  [C805H50]  169.96 75.18 90 top
C147  SCD1U16V2KX-3DLGP  [C402H22]  167.67 75.18 0 top
C149  SCD01U50V2KX-1DLGP  [C402H22]  16.29 142.49 270 top
C150  SC1U10V2KX-1DLGP  [C402H22]  157.01 75.82 180 top
C151  SCD01U50V2KX-1DLGP  [C402H22]  16.29 143.51 270 top
C154  SC10U10V5KX-2DLGP  [C805H50]  168.05 72.14 0 top
C155  SC10U10V5KX-2DLGP  [C805H50]  170.09 72.14 0 top
C157  SC100P50V2JN-3DLGP  [C402H22]  163.48 71.25 0 top
C159  SC100P50V2JN-3DLGP  [C402H22]  162.09 70.74 90 top
C160  SC100P50V2JN-3DLGP  [C402H22]  158.66 71.25 0 top
C163  SCD1U16V2KX-3DLGP  [C402H22]  48.04 108.33 0 top
C170  SC1U10V2KX-1GP  [C402H22]  161.58 64.52 90 top
C186  SCD1U16V2KX-3DLGP  [C402H22]  48.42 99.69 270 top
C190  SC1U16V3KX-4DLGP  [C603H36]  148.5 56.39 180 bottom
C192  SC1U25V3KX-1-DLGP  [C603H36]  162.47 28.45 90 top
C193  SC1U25V3KX-1-DLGP  [C603H36]  162.47 27.18 90 top
C194  SC100P50V2JN-3DLGP  [C402H22]  131.86 60.58 90 top
C197  SCD1U16V2KX-3DLGP  [C402H22]  138.72 56.52 90 top
C198  SCD027U50V3KX-DL-GP  [C603H36]  156.75 24.51 180 top
C199  SCD027U50V3KX-DL-GP  [C603H36]  161.32 32 270 top
C200  SCD027U50V3KX-DL-GP  [C603H36]  161.32 30.73 270 top
C202  SC4D7U6D3V3KX-GP  [C603H36]  40.17 17.27 90 bottom
C203  SC100P50V2JN-3DLGP  [C402H22]  160.94 33.15 270 top
C204  SCD1U16V2KX-3DLGP  [C402H22]  36.13 14.07 270 bottom
C207  SCD01U50V2KX-1DLGP  [C402H22]  47.02 92.96 0 top
C208  SC1U25V3KX-1-DLGP  [C603H36]  156.5 36.58 180 top
C209  SC4D7U6D3V3KX-GP  [C603H36]  47.02 18.54 180 top
C210  SCD027U50V3KX-DL-GP  [C603H36]  155.48 24.51 180 top
C211  SCD1U16V2KX-3DLGP  [C402H22]  148.09 49.02 0 bottom
C213  SCD1U16V2KX-3DLGP  [C402H22]  41.56 20.07 180 top
C214  SCD1U16V2KX-3DLGP  [C402H22]  48.42 87.12 270 top
C216  SCD1U16V2KX-3DLGP  [C402H22]  48.8 118.75 270 top
C222  SCD01U50V3KX-4GP  [C603H36]  141.51 17.91 0 bottom
C223  SCD22U25V3KX-DL-GP  [C603H36]  150.15 26.42 180 top
C224  SCD22U25V3KX-DL-GP  [C603H36]  150.15 34.8 0 top
C225  SCD68U16V3KX-GP-U  [C603H36]  142.27 23.24 270 top
C226  SC1000P50V3JN-DLGP  [C603H36]  142.27 18.41 270 top
C227  SC10U10V5KX-2GP  [C805H54]  87.41 22.61 0 top
C228  SCD22U25V3KX-DL-GP  [C603H36]  150.15 32 180 top
C229  SCD22U25V3KX-DL-GP  [C603H36]  150.15 29.21 0 top
C231  SCD1U16V2KX-3DLGP  [C402H22]  148.12 51.08 180 bottom
C235  SCD68U16V3KX-GP-U  [C603H36]  144.94 23.24 90 top
C236  SC1000P50V3JN-DLGP  [C603H36]  144.94 18.41 90 top
C238  SCD1U16V2KX-3DLGP  [C402H22]  32.04 26.16 180 top
C239  SCD01U50V3KX-4GP  [C603H36]  145.7 17.91 0 bottom
C243  SCD01U50V3KX-4GP  [C603H36]  151.16 17.91 0 bottom
C247  SCD68U16V3KX-GP-U  [C603H36]  150.53 23.24 90 top
C248  SC1000P50V3JN-DLGP  [C603H36]  150.4 18.41 90 top
C249  SCD1U50V3KX-GP  [C603H36]  90.46 24.26 270 top
C255  SCD68U16V3KX-GP-U  [C603H36]  147.61 23.24 270 top
C256  SC1000P50V3JN-DLGP  [C603H36]  147.73 18.41 270 top
C258  SCD1U50V3KX-DL-GP  [C603H35]  66.45 44.07 180 top
C260  SC1U25V3KX-1-DLGP  [C603H36]  66.33 33.78 90 top
C262  SCD01U50V2KX-1GP  [C402H22]  66.2 29.72 90 top
C263  SCD01U50V3KX-4GP  [C603H36]  146.97 17.91 0 bottom
C267  SC100P50V2JN-3DLGP  [C402H22]  83.09 39.62 90 top
C268  SC100P50V2JN-3DLGP  [C402H22]  83.6 38.1 180 top
C283  SC10U10V5KX-2DLGP  [C805H50]  40.42 103 90 bottom
C284  SCD1U16V2KX-3DLGP  [C402H22]  35.69 101.78 90 bottom
C289  SCD1U16V2KX-3DLGP  [C402H22]  40.67 101.55 90 bottom
C290  SCD1U16V2KX-3DLGP  [C402H22]  35.69 100.89 270 bottom
C291  SC22U6D3V5MX-2DLGP  [C805H54]  37.65 102.67 0 bottom
C292  SC10U10V5KX-2DLGP  [C805H50]  32.52 79.83 90 bottom
C293  SCD1U16V2KX-3DLGP  [C402H22]  33.03 82.17 90 bottom
C295  SCD1U16V2KX-3DLGP  [C402H22]  33.71 88.49 90 bottom
C296  SC10U10V5KX-2DLGP  [C805H50]  32.16 101.22 90 bottom
C297  SCD1U16V2KX-3DLGP  [C402H22]  37.45 89.03 180 bottom
C298  SCD1U16V2KX-3DLGP  [C402H22]  33.03 81.28 90 bottom
C299  SCD1U16V2KX-3DLGP  [C402H22]  33.71 89.38 270 bottom
C300  SCD1U16V2KX-3DLGP  [C402H22]  31.53 95.12 270 bottom
C301  SCD1U16V2KX-3DLGP  [C402H22]  31.53 96.01 270 bottom
C302  SCD1U16V2KX-3DLGP  [C402H22]  31.53 96.9 270 bottom
C303  SCD1U16V2KX-3DLGP  [C402H22]  31.53 97.79 270 bottom
C304  SCD1U16V2KX-3DLGP  [C402H22]  31.53 93.09 270 bottom
C305  SCD1U16V2KX-3DLGP  [C402H22]  31.53 92.2 270 bottom
C315  SC10U10V5KX-2GP  [C805H54]  44.99 124.84 90 top
C316  SCD1U16V2KX-3DLGP  [C402H22]  45.37 126.36 270 top
C326  SC180P50V2JN-1DLGP  [C402H22]  79.41 159 90 bottom
C330  SC180P50V2JN-1DLGP  [C402H22]  76.74 160.66 90 bottom
C337  SCD1U16V2KX-3DLGP  [C402H22]  131.35 165.99 90 bottom
C353  SCD1U16V2KX-3DLGP  [C402H22]  131.35 164.08 90 bottom
C356  SC180P50V2JN-1DLGP  [C402H22]  90.08 169.93 270 bottom
C392  SCD1U16V2KX-3DLGP  [C402H22]  131.35 162.18 90 bottom
C395  SC1U10V2KX-1DLGP  [C402H22]  86.14 153.9 270 bottom
C450  SC10U10V5KX-2DLGP  [C805H50]  167.29 88.01 180 bottom
C474  SC10U6D3V3MX-DL-GP  [C603H36]  161.3 81.05 180 bottom
C478  SC10U6D3V3MX-DL-GP  [C603H36]  162.52 81.05 180 bottom
C483  SCD1U16V2KX-3DLGP  [C402H22]  161.07 75.39 270 bottom
C485  SC10U6D3V3MX-DL-GP  [C603H36]  160.08 78.44 0 bottom
C486  SCD1U16V2KX-3DLGP  [C402H22]  48.42 116.2 90 bottom
C489  SCD1U16V2KX-3DLGP  [C402H22]  48.42 90.68 270 top
C493  SC10U6D3V3MX-GP  [C603H38]  160.84 76.45 270 bottom
C495  SCD1U16V2KX-3DLGP  [C402H22]  159.04 76.78 180 bottom
C500  SCD1U16V2KX-3DLGP  [C402H22]  48.42 116.59 270 top
C509  SC10U6D3V3MX-GP  [C603H38]  156.97 74.41 90 bottom
C514  SCD1U16V2KX-3DLGP  [C402H22]  48.42 115.57 270 top
C516  SCD1U16V2KX-3GP  [C402H22]  156.97 73.26 90 bottom
C521  SC1U16V3KX-2GP  [C603H36]  145.12 31.39 270 top
C524  SC2200P50V2KX-2DLGP  [C402H22]  142.43 51.92 0 bottom
C525  SCD1U16V2ZY-2GP  [C402H22]  152.81 49.02 270 bottom
C529  SCD1U16V2KX-3DLGP  [C402H22]  48.17 108.33 180 bottom
C531  SC1KP50V2KX-1GP  [C402H22]  156.75 29.72 270 bottom
C540  SCD1U16V2KX-3DLGP  [C402H22]  48.67 106.81 270 top
C542  SCD1U16V2ZY-2GP  [C402H22]  162.09 43.43 270 top
C543  SC10U25V5KX-DL-GP  [C805H58]  153.2 32.51 180 bottom
C545  SCD1U50V3KX-DL-GP  [C603H35]  153.2 35.81 270 top
C548  SC2D2U6D3V2MX-GP  [C402H22]  159.16 64.14 0 top
C549  SCD1U16V2KX-3DLGP  [C402H22]  158.28 64.14 0 top
C550  SCD1U16V2KX-3DLGP  [C402H22]  160.94 62.74 0 top
C551  SC10U25V5KX-DL-GP  [C805H58]  153.2 28.83 0 bottom
C552  SCD1U50V3KX-DL-GP  [C603H35]  152.18 25.27 180 top
C557  SCD1U16V2KX-3DLGP  [C402H22]  48.42 114.43 90 bottom
C558  SCD1U16V2KX-3DLGP  [C402H22]  138.84 42.42 90 top
C559  SCD1U16V2KX-3DLGP  [C402H22]  64.22 104.52 180 bottom
C562  SC1U10V2KX-1DLGP  [C402H22]  142.65 42.93 90 top
C565  SC22U6D3V5MX-2DLGP  [C805H54]  142.02 41.4 90 top
C570  SCD1U16V2KX-3DLGP  [C402H22]  40.42 13.41 90 bottom
C572  SCD1U16V2KX-3DLGP  [C402H22]  33.05 10.67 0 top
C574  SCD1U16V2KX-3DLGP  [C402H22]  42.45 14.22 90 top
C579  SC2D2U10V3KX-1DLGP-U  [C603H36]  42.96 9.53 270 top
C580  SCD1U16V2KX-3GP  [C402H22]  38.13 12.57 0 bottom
C582  SCD1U16V2KX-3DLGP  [C402H22]  37.5 27.18 90 top
C583  SCD1U16V2KX-3DLGP  [C402H22]  40.42 15.24 90 bottom
C584  SCD1U16V2KX-3DLGP  [C402H22]  40.42 12.52 90 bottom
C585  SCD1U16V2KX-3DLGP  [C402H22]  32.42 28.07 0 top
C587  SCD1U16V2KX-3DLGP  [C402H22]  36.74 17.53 180 bottom
C589  SC1KP50V2KX-1GP  [C402H22]  107.6 29.59 0 top
C591  SC1U10V2KX-1GP  [C402H22]  44.23 5.97 180 bottom
C592  SC10U10V5KX-2DLGP  [C805H50]  24.29 8.38 90 bottom
C593  SC1U10V2KX-1GP  [C402H22]  45.25 5.97 0 top
C595  SCD1U16V2KX-3DLGP  [C402H22]  39.66 5.97 180 bottom
C597  SCD1U50V3KX-DL-GP  [C603H35]  66.33 27.81 90 top
C612  SCD1U16V2KX-3DLGP  [C402H22]  48.42 98.81 270 top
C616  SCD1U16V2KX-3DLGP  [C402H22]  48.42 88.9 270 top
C623  SCD1U16V2KX-3DLGP  [C402H22]  48.42 88.01 270 top
C627  SCD1U16V2KX-3DLGP  [C402H22]  48.42 113.41 90 bottom
C714  SCD1U16V2KX-3DLGP  [C402H22]  107.09 31.11 90 top
C721  SCD1U16V2KX-3DLGP  [C402H22]  107.09 36.45 90 top
C752  SC47P50V2JN-3GP  [C402H22]  97.34 106.79 0 top
C753  SCD1U10V2KX-5GP  [C402H22]  108.03 82.98 180 top
C755  SCD01U50V2KX-1DLGP  [C402H22]  101.13 89.41 0 top
C756  SC12P50V2JN-DL-GP  [C402H22]  97.34 108.82 0 top
C757  SC12P50V2JN-DL-GP  [C402H22]  97.34 110.85 180 top
C758  SC1U10V2KX-1DLGP  [C402H22]  95.28 99.57 0 bottom
C759  SC1U10V2KX-1DLGP  [C402H22]  94.39 99.57 0 bottom
C760  SC1U10V2KX-1DLGP  [C402H22]  78.93 114.07 90 top
C761  SC1U10V2KX-1DLGP  [C402H22]  74.71 114.3 90 bottom
C762  SC120P50V2JN-1-DL-GP  [C402H22]  83.11 87.99 180 bottom
C763  SCD1U16V2KX-3GP  [C402H22]  83.62 83.93 180 bottom
C764  SCD1U16V2KX-3GP  [C402H22]  77.15 83.93 0 top
C765  SC1U10V2KX-1DLGP  [C402H22]  79.15 105.03 270 bottom
C766  SC1U10V2KX-1DLGP  [C402H22]  79.15 105.92 270 bottom
C767  SC1U10V2KX-1DLGP  [C402H22]  74.33 98.55 90 bottom
C768  SC1U10V2KX-1DLGP  [C402H22]  79.15 104.14 270 bottom
C769  SC1U10V2KX-1DLGP  [C402H22]  76.51 92.31 180 bottom
C770  SC1U10V2KX-1DLGP  [C402H22]  75.11 101.83 90 bottom
C771  SC4D7U6D3V3KX-DLGP  [C603H36]  48.17 83.95 90 bottom
C772  SC22U6D3V5MX-2DLGP  [C805H54]  48.04 85.6 90 bottom
C773  SC1U10V2KX-1DLGP  [C402H22]  74.73 100.31 90 bottom
C774  SCD1U16V2KX-3DLGP  [C402H22]  78.9 96.9 270 bottom
C775  SC1U10V2KX-1DLGP  [C402H22]  77.88 93.73 270 bottom
C776  SC1U10V2KX-1DLGP  [C402H22]  62.39 96.9 0 bottom
C777  SC1U10V2KX-1DLGP  [C402H22]  61.52 102.72 90 bottom
C778  SC1U10V2KX-1DLGP  [C402H22]  64.22 101.73 0 bottom
C779  SC1U10V2KX-1DLGP  [C402H22]  87.66 102.52 180 bottom
C780  SC4D7U6D3V3KX-DLGP  [C603H36]  91.5 103.48 180 bottom
C781  SCD1U16V2KX-3DLGP  [C402H22]  88.55 102.52 180 bottom
C782  SC1U10V2KX-1DLGP  [C402H22]  87.66 99.98 180 bottom
C783  SC1U10V2KX-1DLGP  [C402H22]  88.57 99.98 180 bottom
C784  SC4D7U6D3V3KX-DLGP  [C603H36]  90.35 100.06 270 bottom
C785  SC1U10V2KX-1DLGP  [C402H22]  72.95 85.58 270 top
C786  SC1U10V2KX-1DLGP  [C402H22]  79.41 88.65 270 bottom
C787  SC4D7U6D3V3KX-DLGP  [C603H36]  72.57 83.55 270 top
C788  SC4D7U6D3V3KX-DLGP  [C603H36]  75.37 83.55 90 top
C789  SCD1U16V2KX-3DLGP  [C402H22]  72.95 84.69 270 top
C790  SCD1U16V2KX-3DLGP  [C402H22]  79.41 89.53 270 bottom
C791  SCD1U16V2KX-3DLGP  [C402H22]  79.41 90.42 270 bottom
C792  SCD1U16V2KX-3DLGP  [C402H22]  74.99 84.69 90 top
C793  SC1U10V2KX-1DLGP  [C402H22]  74.99 85.58 90 top
C794  SC1U10V2KX-1DLGP  [C402H22]  98.08 112.39 90 top
C795  SC1U10V2KX-1DLGP  [C402H22]  98.08 113.28 90 top
C796  SC1U10V2KX-1DLGP  [C402H22]  98.08 114.17 90 top
C797  SC4D7U6D3V3KX-DLGP  [C603H36]  98.2 115.32 90 top
C798  SC1U10V2KX-1DLGP  [C402H22]  81.34 103.38 90 bottom
C799  SC1U10V2KX-1DLGP  [C402H22]  80.68 107.57 270 bottom
C800  SC1U10V2KX-1DLGP  [C402H22]  81.31 106.68 270 bottom
C801  SC1U10V2KX-1DLGP  [C402H22]  81.82 105.16 0 bottom
C802  SC1U10V2KX-1DLGP  [C402H22]  82.71 105.16 0 bottom
C803  SC1U10V2KX-1DLGP  [C402H22]  83.6 105.16 0 bottom
C804  SC4D7U6D3V3KX-DLGP  [C603H36]  84.62 105.54 0 bottom
C805  SC1U10V2KX-1DLGP  [C402H22]  86.9 98.55 270 bottom
C806  SC1U10V2KX-1DLGP  [C402H22]  79.15 99.6 180 bottom
C807  SC1U10V2KX-1DLGP  [C402H22]  79.66 98.17 90 bottom
C808  SC1U10V2KX-1DLGP  [C402H22]  84.49 94.74 180 bottom
C809  SC1U10V2KX-1DLGP  [C402H22]  83.6 108.84 180 bottom
C810  SC4D7U6D3V3KX-DLGP  [C603H36]  80.93 110.62 0 bottom
C811  SC4D7U6D3V3KX-DLGP  [C603H36]  82.2 110.62 0 bottom
C812  SC22U6D3V3MX-1-DL-GP  [C603H40]  79.18 102.34 0 bottom
C813  SC1U10V2KX-1DLGP  [C402H22]  86.01 95.25 270 bottom
C814  SC1U10V2KX-1DLGP  [C402H22]  86.77 96.9 270 bottom
C815  SC1U10V2KX-1DLGP  [C402H22]  85.38 100.08 270 bottom
C816  SC1U10V2KX-1DLGP  [C402H22]  82.58 101.73 270 bottom
C817  SC1U10V2KX-1DLGP  [C402H22]  83.6 98.17 90 bottom
C818  SC1U10V2KX-1DLGP  [C402H22]  84.61 96.33 270 bottom
C819  SC1U10V2KX-1DLGP  [C402H22]  84.61 97.29 270 bottom
C820  SCD1U16V2KX-3DLGP  [C402H22]  83.35 100.08 90 bottom
C821  SCD1U16V2KX-3DLGP  [C402H22]  86.16 101.71 270 bottom
C822  SC22U6D3V3MX-1-DL-GP  [C603H40]  82.71 95.12 90 bottom
C823  SC1U10V2KX-1DLGP  [C402H22]  81.63 98.17 270 bottom
C824  SC1U10V2KX-1DLGP  [C402H22]  81.06 96.52 270 bottom
C825  SC1U10V2KX-1DLGP  [C402H22]  88.95 95.99 90 bottom
C826  SCD1U16V2KX-3DLGP  [C402H22]  88.95 96.88 90 bottom
C827  SC1U10V2KX-1DLGP  [C402H22]  90.86 95.99 270 bottom
C828  SC4D7U6D3V3KX-DLGP  [C603H36]  88.7 94.98 90 bottom
C829  SCD1U16V2KX-3DLGP  [C402H22]  90.96 96.88 270 bottom
C830  SC4D7U6D3V3KX-DLGP  [C603H36]  90.73 94.21 180 bottom
C835  SC1U10V2KX-1DLGP  [C402H22]  46.13 114.05 180 top
C836  SCD1U10V2KX-4GP  [C402H20]  162.69 92.13 0 top
C839  SC68P50V2JN-1GP  [C402H22]  83.88 91.93 0 bottom
C852  SC10U10V5KX-2GP  [C805H54]  107.48 85.72 0 top
C853  SCD1U16V2KX-3DLGP  [C402H22]  107.98 88.52 180 top
C857  SCD1U50V3KX-GP  [C603H36]  51.72 138.05 0 top
C859  SC1000P50V3JN-DLGP  [C603H36]  109.13 91.82 270 top
C862  SCD1U50V3KX-GP  [C603H36]  42.58 127.76 0 top
C863  SC1U10V2KX-1GP  [C402H22]  39.66 5.97 0 top
C864  SC1U10V2KX-1GP  [C402H22]  128.07 217.96 270 top
C865  SCD22U25V3KX-DL-GP  [C603H36]  38.77 143 270 top
C866  SC1U10V2KX-1GP  [C402H22]  92.62 14.86 180 bottom
C869  SCD1U16V2KX-3DLGP  [C402H22]  42.68 120.83 270 top
C871  SC1U10V2KX-1GP  [C402H22]  161.2 112.01 270 top
C872  SCD068U16V2KX-DL-GP  [C402H22]  108.75 18.41 0 top
C1491  SC1U10V2KX-1DLGP  [C402H22]  157.39 78.36 180 top
C1608  SC1KP50V2KX-1DLGP  [C402H22]  95.28 168.4 90 bottom
C1609  SCD1U16V2KX-3DLGP  [C402H22]  95.28 167.39 270 bottom
C1615  SC2D2U10V3KX-1DLGP-U  [C603H36]  128.56 208.66 270 bottom
C1616  SC1U10V2KX-1GP  [C402H22]  124.49 211.2 0 bottom
C1617  SCD1U16V2KX-3DLGP  [C402H22]  128.43 209.68 270 bottom
C1638  SC1U10V2KX-1DLGP  [C402H22]  88.04 138.18 90 top
C1639  SC1U10V2KX-1DLGP  [C402H22]  88.04 139.06 90 top
C1644  SC22U6D3V3MX-1-DL-GP  [C603H40]  79.03 160.66 270 bottom
C1645  SC22U6D3V3MX-1-DL-GP  [C603H40]  81.69 160.66 270 bottom
C1646  SC22U6D3V3MX-1-DL-GP  [C603H40]  76.23 168.4 0 bottom
C1647  SC22U6D3V3MX-1-DL-GP  [C603H40]  87.03 160.66 270 bottom
C1648  SC22U6D3V3MX-1-DL-GP  [C603H40]  84.36 160.66 270 bottom
C1649  SC22U6D3V3MX-1-DL-GP  [C603H40]  87.03 167.77 270 bottom
C1650  SC22U6D3V3MX-1-DL-GP  [C603H40]  84.36 167.77 270 bottom
C1651  SC22U6D3V3MX-1-DL-GP  [C603H40]  81.69 167.77 270 bottom
C1652  SC22U6D3V3MX-1-DL-GP  [C603H40]  79.03 167.77 270 bottom
C1653  SC22U6D3V3MX-1-DL-GP  [C603H40]  81.69 157.99 270 bottom
C1654  SC22U6D3V3MX-1-DL-GP  [C603H40]  84.36 157.99 90 bottom
C1655  SC22U6D3V3MX-1-DL-GP  [C603H40]  87.03 157.99 270 bottom
C1656  SC22U6D3V3MX-1-DL-GP  [C603H40]  79.03 157.99 90 bottom
C1657  SCD22U10V2KX-2-GP  [C402H22]  86.65 165.61 270 bottom
C1658  SCD22U10V2KX-2-GP  [C402H22]  84.23 165.61 270 bottom
C1659  SCD22U10V2KX-2-GP  [C402H22]  84.23 163.19 270 bottom
C1660  SCD22U10V2KX-2-GP  [C402H22]  79.41 163.19 270 bottom
C1661  SCD22U10V2KX-2-GP  [C402H22]  81.82 163.19 270 bottom
C1662  SCD22U10V2KX-2-GP  [C402H22]  81.82 165.61 270 bottom
C1663  SCD22U10V2KX-2-GP  [C402H22]  86.65 163.19 270 bottom
C1664  SCD22U10V2KX-2-GP  [C402H22]  79.41 165.61 270 bottom
C1665  SCD22U10V2KX-2-GP  [C402H22]  86.65 156.59 270 bottom
C1666  SCD22U10V2KX-2-GP  [C402H22]  81.82 155.7 90 bottom
C1667  SCD22U10V2KX-2-GP  [C402H22]  81.82 156.59 90 bottom
C1668  SCD22U10V2KX-2-GP  [C402H22]  79.41 156.59 90 bottom
C1669  SCD22U10V2KX-2-GP  [C402H22]  84.23 156.59 90 bottom
C1670  SCD22U10V2KX-2-GP  [C402H22]  86.65 159 270 bottom
C1671  SCD22U10V2KX-2-GP  [C402H22]  84.23 159 90 bottom
C1672  SCD22U10V2KX-2-GP  [C402H22]  81.82 159 270 bottom
C1673  SC22U6D3V3MX-1-DL-GP  [C603H40]  45.5 128.52 90 top
C1674  SC10U6D3V3MX-DL-GP  [C603H36]  84.11 155.17 270 bottom
C1677  SC10U6D3V3MX-DL-GP  [C603H36]  75.98 152.65 90 bottom
C1678  SC22U6D3V3MX-1-DL-GP  [C603H40]  90.58 164.08 90 bottom
C1679  SC22U6D3V3MX-1-DL-GP  [C603H40]  90.58 161.67 90 bottom
C1680  SC22U6D3V3MX-1-DL-GP  [C603H40]  90.46 168.91 90 bottom
C1681  SC22U6D3V3MX-1-DL-GP  [C603H40]  90.46 166.5 90 bottom
C1682  SC22U6D3V3MX-1-DL-GP  [C603H40]  90.58 159.38 90 bottom
C1683  SC22U6D3V3MX-1-DL-GP  [C603H40]  91.47 156.46 180 bottom
C1684  SC22U6D3V3MX-1-DL-GP  [C603H40]  95.16 156.46 180 bottom
C1685  SC22U6D3V3MX-1-DL-GP  [C603H40]  93.25 156.46 180 bottom
C1686  SC22U6D3V3MX-1-DL-GP  [C603H40]  93.02 172.09 0 bottom
C1687  SC22U6D3V3MX-1-DL-GP  [C603H40]  94.9 172.09 0 bottom
C1688  SC22U6D3V3MX-1-DL-GP  [C603H40]  91.85 172.09 0 bottom
C1689  SCD22U10V2KX-2-GP  [C402H22]  90.08 167.64 270 bottom
C1690  SCD22U10V2KX-2-GP  [C402H22]  90.2 165.23 270 bottom
C1691  SCD22U10V2KX-2-GP  [C402H22]  90.2 162.81 270 bottom
C1692  SCD22U10V2KX-2-GP  [C402H22]  90.2 160.53 270 bottom
C1693  SCD22U10V2KX-2-GP  [C402H22]  90.2 158.24 270 bottom
C1694  SCD22U10V2KX-2-GP  [C402H22]  90.08 170.81 270 bottom
C1695  SC10U6D3V3MX-DL-GP  [C603H36]  88.93 151.51 0 bottom
C1696  SCD22U10V2KX-2-GP  [C402H22]  72.68 161.42 90 bottom
C1697  SC180P50V2JN-1DLGP  [C402H22]  84.62 150.24 180 bottom
C1698  SC1U10V2KX-1DLGP  [C402H22]  92.87 12.83 0 top
C1699  SC1U10V2KX-1DLGP  [C402H22]  87.79 12.83 0 top
C1700  SC1U6D3V2KX-DLGP  [C402H22]  91.75 16.1 180 top
C1701  SCD1U16V2KX-3DLGP  [C402H22]  87.79 10.79 180 top
C1702  SC10U6D3V3MX-DL-GP  [C603H36]  39.91 144.27 270 top
C1703  SCD22U10V2KX-2-GP  [C402H22]  78.01 154.81 180 bottom
C1704  SC10U6D3V3MX-DL-GP  [C603H36]  87.66 151.51 0 bottom
C1705  SC10U6D3V3MX-DL-GP  [C603H36]  91.98 151.51 0 bottom
C1706  SC10U6D3V3MX-DL-GP  [C603H36]  106.71 150.37 0 bottom
C1707  SC10U6D3V3MX-DL-GP  [C603H36]  90.58 151.51 0 bottom
C1708  SCD22U10V2KX-2-GP  [C402H22]  95.16 151.89 0 bottom
C1714  SC10U6D3V3MX-DL-GP  [C603H36]  87.92 154.94 270 bottom
C1715  SC10U6D3V3MX-DL-GP  [C603H36]  82.84 148.84 90 bottom
C1716  SCD22U10V2KX-2-GP  [C402H22]  81.31 154.81 90 bottom
C1721  SC150P50V2KX-GP  [C402H22]  78.9 186.56 0 top
C1722  SC150P50V2KX-GP  [C402H22]  83.98 190.63 0 top
C1723  SCD1U16V2KX-3DLGP  [C402H22]  131.35 154.94 90 bottom
C1724  SC4D7U6D3V3KX-DLGP  [C603H36]  150.27 128.14 0 bottom
C1725  SC4D7U6D3V3KX-DLGP  [C603H36]  130.97 153.03 90 bottom
C1726  SCD1U10V2KX-5GP  [C402H22]  154.34 181.61 270 bottom
C1727  SC1KP50V2KX-1DLGP  [C402H22]  138.72 191.9 180 bottom
C1728  SC1U10V2KX-1DLGP  [C402H22]  140.5 191.9 0 bottom
C1729  SCD1U16V2KX-3GP  [C402H22]  130.97 127.25 90 bottom
C1730  SCD1U16V2KX-3GP  [C402H22]  130.34 128.27 90 bottom
C1731  SCD1U16V2KX-3DLGP  [C402H22]  139.61 191.9 180 bottom
C1732  SCD1U16V2KX-3DLGP  [C402H22]  149.13 128.14 0 bottom
C1733  SC100P50V2JN-3GP  [C402H22]  77.27 148.74 90 bottom
C1734  SC100P50V2JN-3GP  [C402H22]  80.93 135.13 270 top
C1735  SCD01U25V2KX-3GP  [C402H22]  56.8 159.64 270 top
C1736  SC1U10V2KX-1DLGP  [C402H22]  159.8 111.51 180 top
C1737  SCD1U16V2KX-3DLGP  [C402H22]  156.88 123.19 0 top
C1738  SC150P50V2JN-3DLGP  [C402H22]  54.77 149.1 0 top
C1739  SC1U10V2KX-1GP  [C402H22]  100.11 210.57 270 top
C1741  SCD22U10V2KX-2-GP  [C402H22]  84.13 153.62 180 bottom
C1742  SCD1U16V2KX-3DLGP  [C402H22]  122.08 224.54 90 top
C1743  SC10U6D3V3MX-DL-GP  [C603H36]  123.73 202.31 180 bottom
C1744  SC10U6D3V3MX-DL-GP  [C603H36]  125 202.31 180 bottom
C1745  SC2D2U10V3KX-1DLGP-U  [C603H36]  126.27 202.31 180 bottom
C1746  SCD1U16V2KX-3DLGP  [C402H22]  146.59 150.88 0 bottom
C1747  SCD1U16V2KX-3GP  [C402H22]  96.43 26.42 0 top
C1748  SC10U10V5KX-2GP  [C805H54]  100.36 24 90 top
C1752  SC10U10V5KX-2GP  [C805H54]  100.36 27.05 90 top
C1753  SCD1U16V2KX-3DLGP  [C402H22]  173.26 107.31 270 top
C1754  SCD1U16V2KX-3DLGP  [C402H22]  95.54 26.42 180 top
C1755  SCD068U16V2KX-DL-GP  [C402H22]  100.36 25.53 270 top
C1756  SC1KP50V2KX-1GP  [C402H22]  175.17 125.73 0 top
C1757  SCD1U16V2KX-3DLGP  [C402H22]  163.1 118.49 90 top
C1758  SCD1U16V2KX-3DLGP  [C402H22]  38.13 119.89 180 top
C1760  SCD1U16V2KX-3GP  [C402H22]  27.08 28.19 270 bottom
C1764  SCD01U50V2KX-1DLGP  [C402H22]  92.87 23.62 90 top
C1768  SCD1U25V3KX-GP  [C603H36]  58.71 143.64 180 top
C1769  SCD1U16V2KX-3DLGP  [C402H22]  90.08 23.11 90 top
C1770  SC10U10V5KX-2DLGP  [C805H50]  157.64 188.67 90 bottom
C1771  SC10U10V5KX-2DLGP  [C805H50]  157.64 190.68 90 bottom
C1773  SC10P50V2JN-4GP  [C402H22]  31.33 12.7 0 bottom
C1774  SC10P50V2JN-4GP  [C402H22]  32.21 12.7 0 bottom
C1780  SC100P50V2JN-3DLGP  [C402H22]  164.19 85.45 0 bottom
C1796  SC1U16V3KX-2GP  [C603H36]  143.8 73.15 0 top
C1797  SC1U16V3KX-2GP  [C603H36]  143.04 77.72 0 bottom
C1798  SC1U10V2KX-1GP  [C402H22]  33.82 7.98 180 bottom
C1799  SC15P50V2JN-DL-GP  [C402H22]  37.75 10.29 90 top
C1800  SC12P50V2JN-DL-GP  [C402H22]  34.83 10.54 270 top
C1801  SC1U25V3KX-1-DLGP  [C603H36]  36.3 13.06 270 bottom
C1802  SC2D2U10V3KX-1DLGP-U  [C603H36]  71.28 29.08 90 top
C1803  SC4D7U6D3V3KX-GP  [C603H36]  46.26 15.88 270 top
C1804  SC4D7U6D3V3KX-GP  [C603H36]  48.29 18.54 180 top
C1805  SCD1U16V2KX-3DLGP  [C402H22]  35.47 20.07 180 top
C1806  SCD1U16V2KX-3DLGP  [C402H22]  71.28 30.23 90 top
C1807  SCD1U25V3KX-GP  [C603H36]  46.26 14.61 270 top
C1808  SCD1U16V2KX-3DLGP  [C402H22]  34.58 20.07 180 top
C1809  SCD1U16V2KX-3DLGP  [C402H22]  65.44 179.71 270 top
C1810  SCD1U16V2KX-3DLGP  [C402H22]  65.44 181.48 270 top
C1811  SCD1U16V2KX-3DLGP  [C402H22]  65.44 178.82 270 top
C1812  SCD1U16V2KX-3DLGP  [C402H22]  65.44 183.26 270 top
C1813  SCD1U16V2KX-3DLGP  [C402H22]  65.44 180.59 270 top
C1814  SCD1U16V2KX-3DLGP  [C402H22]  65.44 182.37 270 top
C1815  SCD1U16V2KX-3DLGP  [C402H22]  65.44 184.15 270 top
C1816  SCD1U16V2KX-3DLGP  [C402H22]  138.72 45.59 180 top
C1817  SCD1U16V2KX-3DLGP  [C402H22]  139.1 49.15 270 bottom
C1818  SCD1U16V2KX-3DLGP  [C402H22]  139.1 49.15 90 top
C1820  SCD1U16V2KX-3DLGP  [C402H22]  144.43 60.33 0 bottom
C1821  SC1U10V2KX-1DLGP  [C402H22]  142.91 58.29 270 bottom
C1823  SCD1U16V2ZY-2GP  [C402H22]  120.25 48.77 270 top
C1824  SC22U6D3V5MX-2DLGP  [C805H54]  159.29 44.07 180 bottom
C1825  SC1U10V2KX-1DLGP  [C402H22]  139.1 50.11 90 bottom
C1826  SCD1U16V2KX-3DLGP  [C402H22]  158.4 46.35 270 bottom
C1827  SC1U10V2KX-1GP  [C402H22]  39 86.49 180 bottom
C1828  SCD22U10V2KX-2-GP  [C402H22]  76.61 154.05 90 bottom
C1829  SC1U10V2KX-1DLGP  [C402H22]  141.94 8.31 270 top
C1830  SC1U10V2KX-1DLGP  [C402H22]  142.2 5.64 270 top
C1831  SC1U6D3V2KX-DLGP  [C402H22]  141.94 9.19 270 top
C1832  SCD1U16V2KX-3DLGP  [C402H22]  149.59 8.38 90 top
C1833  SC10U10V5KX-2GP  [C805H54]  146.21 10.16 0 bottom
C1834  SCD1U16V2KX-3DLGP  [C402H22]  149.59 5.71 90 top
C1835  SC10U10V5KX-2GP  [C805H54]  149.13 10.16 0 bottom
C1836  SC1KP50V2KX-1DLGP  [C402H22]  149.59 6.6 90 top
C1837  SC1KP50V2KX-1DLGP  [C402H22]  149.59 7.49 90 top
C1838  SCD1U16V2KX-3DLGP  [C402H22]  89.57 115.7 0 bottom
C1839  SCD1U16V2KX-3DLGP  [C402H22]  88.55 115.7 0 bottom
C1840  SCD1U16V2KX-3DLGP  [C402H22]  90.46 115.7 0 bottom
C1841  SCD1U16V2KX-3DLGP  [C402H22]  85.76 115.7 0 bottom
C1842  SCD1U16V2KX-3DLGP  [C402H22]  87.66 115.7 0 bottom
C1843  SCD1U16V2KX-3DLGP  [C402H22]  84.74 115.7 0 bottom
C1844  SCD1U16V2KX-3DLGP  [C402H22]  86.65 115.7 0 bottom
C1845  SCD1U16V2KX-3DLGP  [C402H22]  83.85 115.7 0 bottom
C1846  SCD1U10V2KX-5GP  [C402H22]  92.44 97.08 180 bottom
C1847  SCD082U16V2KX-1-GP  [C402H22]  93.89 101.6 180 bottom
C1848  SCD68U16V3KX-3-GP  [C603H38]  101 101.35 0 top
C1849  SCD082U16V2KX-GP  [C402H22]  93.93 103.59 180 bottom
C1850  SCD01U50V2KX-1DLGP  [C402H22]  98.71 99.06 90 top
C1851  SCD1U16V2KX-3DLGP  [C402H22]  48.67 105.79 270 top
C1852  SCD1U16V2KX-3DLGP  [C402H22]  48.67 104.9 270 top
C1853  SCD1U16V2KX-3DLGP  [C402H22]  48.42 89.79 270 top
C1854  SCD1U16V2KX-3DLGP  [C402H22]  47.02 114.05 180 top
C1855  SCD01U50V2KX-1DLGP  [C402H22]  47.3 111.99 180 top
C1856  SCD1U16V2KX-3DLGP  [C402H22]  48.67 103.12 270 top
C1857  SCD1U16V2KX-3DLGP  [C402H22]  48.42 112.39 90 bottom
C1858  SC10U6D3V3MX-DL-GP  [C603H36]  48.47 85.72 270 top
C1859  SCD1U16V2KX-3DLGP  [C402H22]  48.42 89.66 90 bottom
C1860  SCD1U16V2KX-3DLGP  [C402H22]  46.77 96.27 0 bottom
C1861  SCD1U16V2KX-3DLGP  [C402H22]  47.79 96.14 180 top
C1864  SCD01U50V2KX-1DLGP  [C402H22]  163.81 90.22 180 top
C1867  SC1U10V2KX-1DLGP  [C402H22]  47.28 91.19 180 bottom
C1868  SCD1U16V2KX-3DLGP  [C402H22]  46.39 91.19 180 bottom
C1869  SCD1U16V2KX-3DLGP  [C402H22]  48.44 94.76 90 bottom
C1870  SCD01U50V2KX-1DLGP  [C402H22]  100.11 211.84 90 top
C1871  SC180P50V2JN-1DLGP  [C402H22]  137.19 154.94 90 bottom
C1872  SCD22U10V2KX-2-GP  [C402H22]  137.19 160.27 90 bottom
C1873  SCD22U10V2KX-2-GP  [C402H22]  137.19 156.84 90 bottom
C1874  SCD22U10V2KX-2-GP  [C402H22]  137.19 162.18 90 bottom
C1875  SCD22U10V2KX-2-GP  [C402H22]  137.19 164.08 90 bottom
C1876  SC180P50V2JN-1DLGP  [C402H22]  137.19 165.99 90 bottom
C1877  SCD1U16V2KX-3DLGP  [C402H22]  38.41 76.15 0 bottom
C1925  SC10U10V5KX-2GP  [C805H54]  88.43 6.86 0 top
C1926  SCD1U16V2KX-3DLGP  [C402H22]  92.87 10.79 180 top
C1927  SC10U10V5KX-2GP  [C805H54]  92.24 6.86 0 top
C1928  SC1KP50V2KX-1DLGP  [C402H22]  89.82 7.62 0 top
C1929  SC1KP50V2KX-1DLGP  [C402H22]  90.84 7.62 0 top
C1930  SCD1U16V2KX-3GP  [C402H22]  85.76 209.17 180 bottom
C1934  SC22U6D3V3MX-1-DL-GP  [C603H40]  79.03 170.31 270 bottom
C1935  SC22U6D3V3MX-1-DL-GP  [C603H40]  81.69 170.31 270 bottom
C1936  SC22U6D3V3MX-1-DL-GP  [C603H40]  84.36 170.31 270 bottom
C1937  SC180P50V2JN-1GP  [C402H22]  83.6 172.34 270 bottom
C1938  SC22U6D3V3MX-1-DL-GP  [C603H40]  87.03 170.31 270 bottom
C1939  SCD22U10V2KX-2-GP  [C402H22]  85.76 172.34 270 bottom
C1940  SCD22U10V2KX-2-GP  [C402H22]  87.79 172.34 270 bottom
C1941  SCD22U10V2KX-2-GP  [C402H22]  81.19 172.34 270 bottom
C1942  SCD22U10V2KX-2-GP  [C402H22]  87.79 173.23 270 bottom
C1943  SCD22U10V2KX-2-GP  [C402H22]  78.9 172.34 270 bottom
C1944  SCD22U10V2KX-2-GP  [C402H22]  85.76 173.23 270 bottom
C1945  SCD22U10V2KX-2-GP  [C402H22]  83.6 173.23 270 bottom
C1946  SCD22U10V2KX-2-GP  [C402H22]  81.19 173.23 270 bottom
C1947  SC22U6D3V3MX-1-DL-GP  [C603H40]  79.03 174.88 270 bottom
C1948  SC22U6D3V3MX-1-DL-GP  [C603H40]  81.69 174.88 270 bottom
C1949  SC22U6D3V3MX-1-DL-GP  [C603H40]  87.03 174.88 270 bottom
C1950  SC22U6D3V3MX-1-DL-GP  [C603H40]  76.49 176.53 0 bottom
C1951  SC22U6D3V3MX-1-DL-GP  [C603H40]  84.36 174.88 270 bottom
C1952  SCD22U10V2KX-2-GP  [C402H22]  78.9 173.23 270 bottom
C1953  SC10U6D3V3MX-GP  [C603H38]  79.03 153.42 180 bottom
C1954  SCD22U10V2KX-2-GP  [C402H22]  79.41 155.57 90 bottom
C1956  SC10U6D3V3MX-GP  [C603H38]  160.56 215.39 0 bottom
C1957  SC1U10V2KX-1GP  [C402H22]  76.44 151.54 90 bottom
C1958  SCD1U10V2KX-5GP  [C402H22]  154.34 184.66 270 bottom
C1959  SC1KP50V2KX-1DLGP  [C402H22]  147.23 191.9 0 bottom
C1960  SC1U10V2KX-1DLGP  [C402H22]  148.12 191.9 0 bottom
C1961  SCD1U16V2KX-3DLGP  [C402H22]  154.72 165.99 270 bottom
C1962  SC180P50V2JN-1DLGP  [C402H22]  154.72 164.08 270 bottom
C1963  SCD22U10V2KX-2-GP  [C402H22]  154.72 162.18 270 bottom
C1964  SCD22U10V2KX-2-GP  [C402H22]  154.72 156.97 270 bottom
C1965  SCD22U10V2KX-2-GP  [C402H22]  154.72 154.94 270 bottom
C1966  SCD1U16V2KX-3DLGP  [C402H22]  154.72 159.38 270 bottom
C1967  SCD1U16V2KX-3DLGP  [C402H22]  148.62 165.99 270 bottom
C1968  SCD1U16V2KX-3DLGP  [C402H22]  148.62 164.08 270 bottom
C1969  SCD1U16V2KX-3DLGP  [C402H22]  148.62 162.18 270 bottom
C1970  SCD1U16V2KX-3DLGP  [C402H22]  148.62 156.97 270 bottom
C1971  SC4D7U6D3V3KX-DLGP  [C603H36]  136.94 127.25 180 bottom
C1972  SC4D7U6D3V3KX-DLGP  [C603H36]  154.97 153.03 270 bottom
C1973  SC4D7U6D3V3KX-DLGP  [C603H36]  147.99 153.03 270 bottom
C1974  SCD22U10V2KX-2-GP  [C402H22]  148.62 160.27 270 bottom
C1975  SCD1U16V2KX-3GP  [C402H22]  146.08 128.14 270 bottom
C1976  SCD1U16V2KX-3GP  [C402H22]  142.65 125.98 90 bottom
C1977  SCD1U16V2KX-3DLGP  [C402H22]  138.72 127.25 180 bottom
C1978  SC180P50V2JN-1DLGP  [C402H22]  148.62 154.94 270 bottom
C1979  SCD1U16V2KX-3DLGP  [C402H22]  152.18 150.88 0 bottom
